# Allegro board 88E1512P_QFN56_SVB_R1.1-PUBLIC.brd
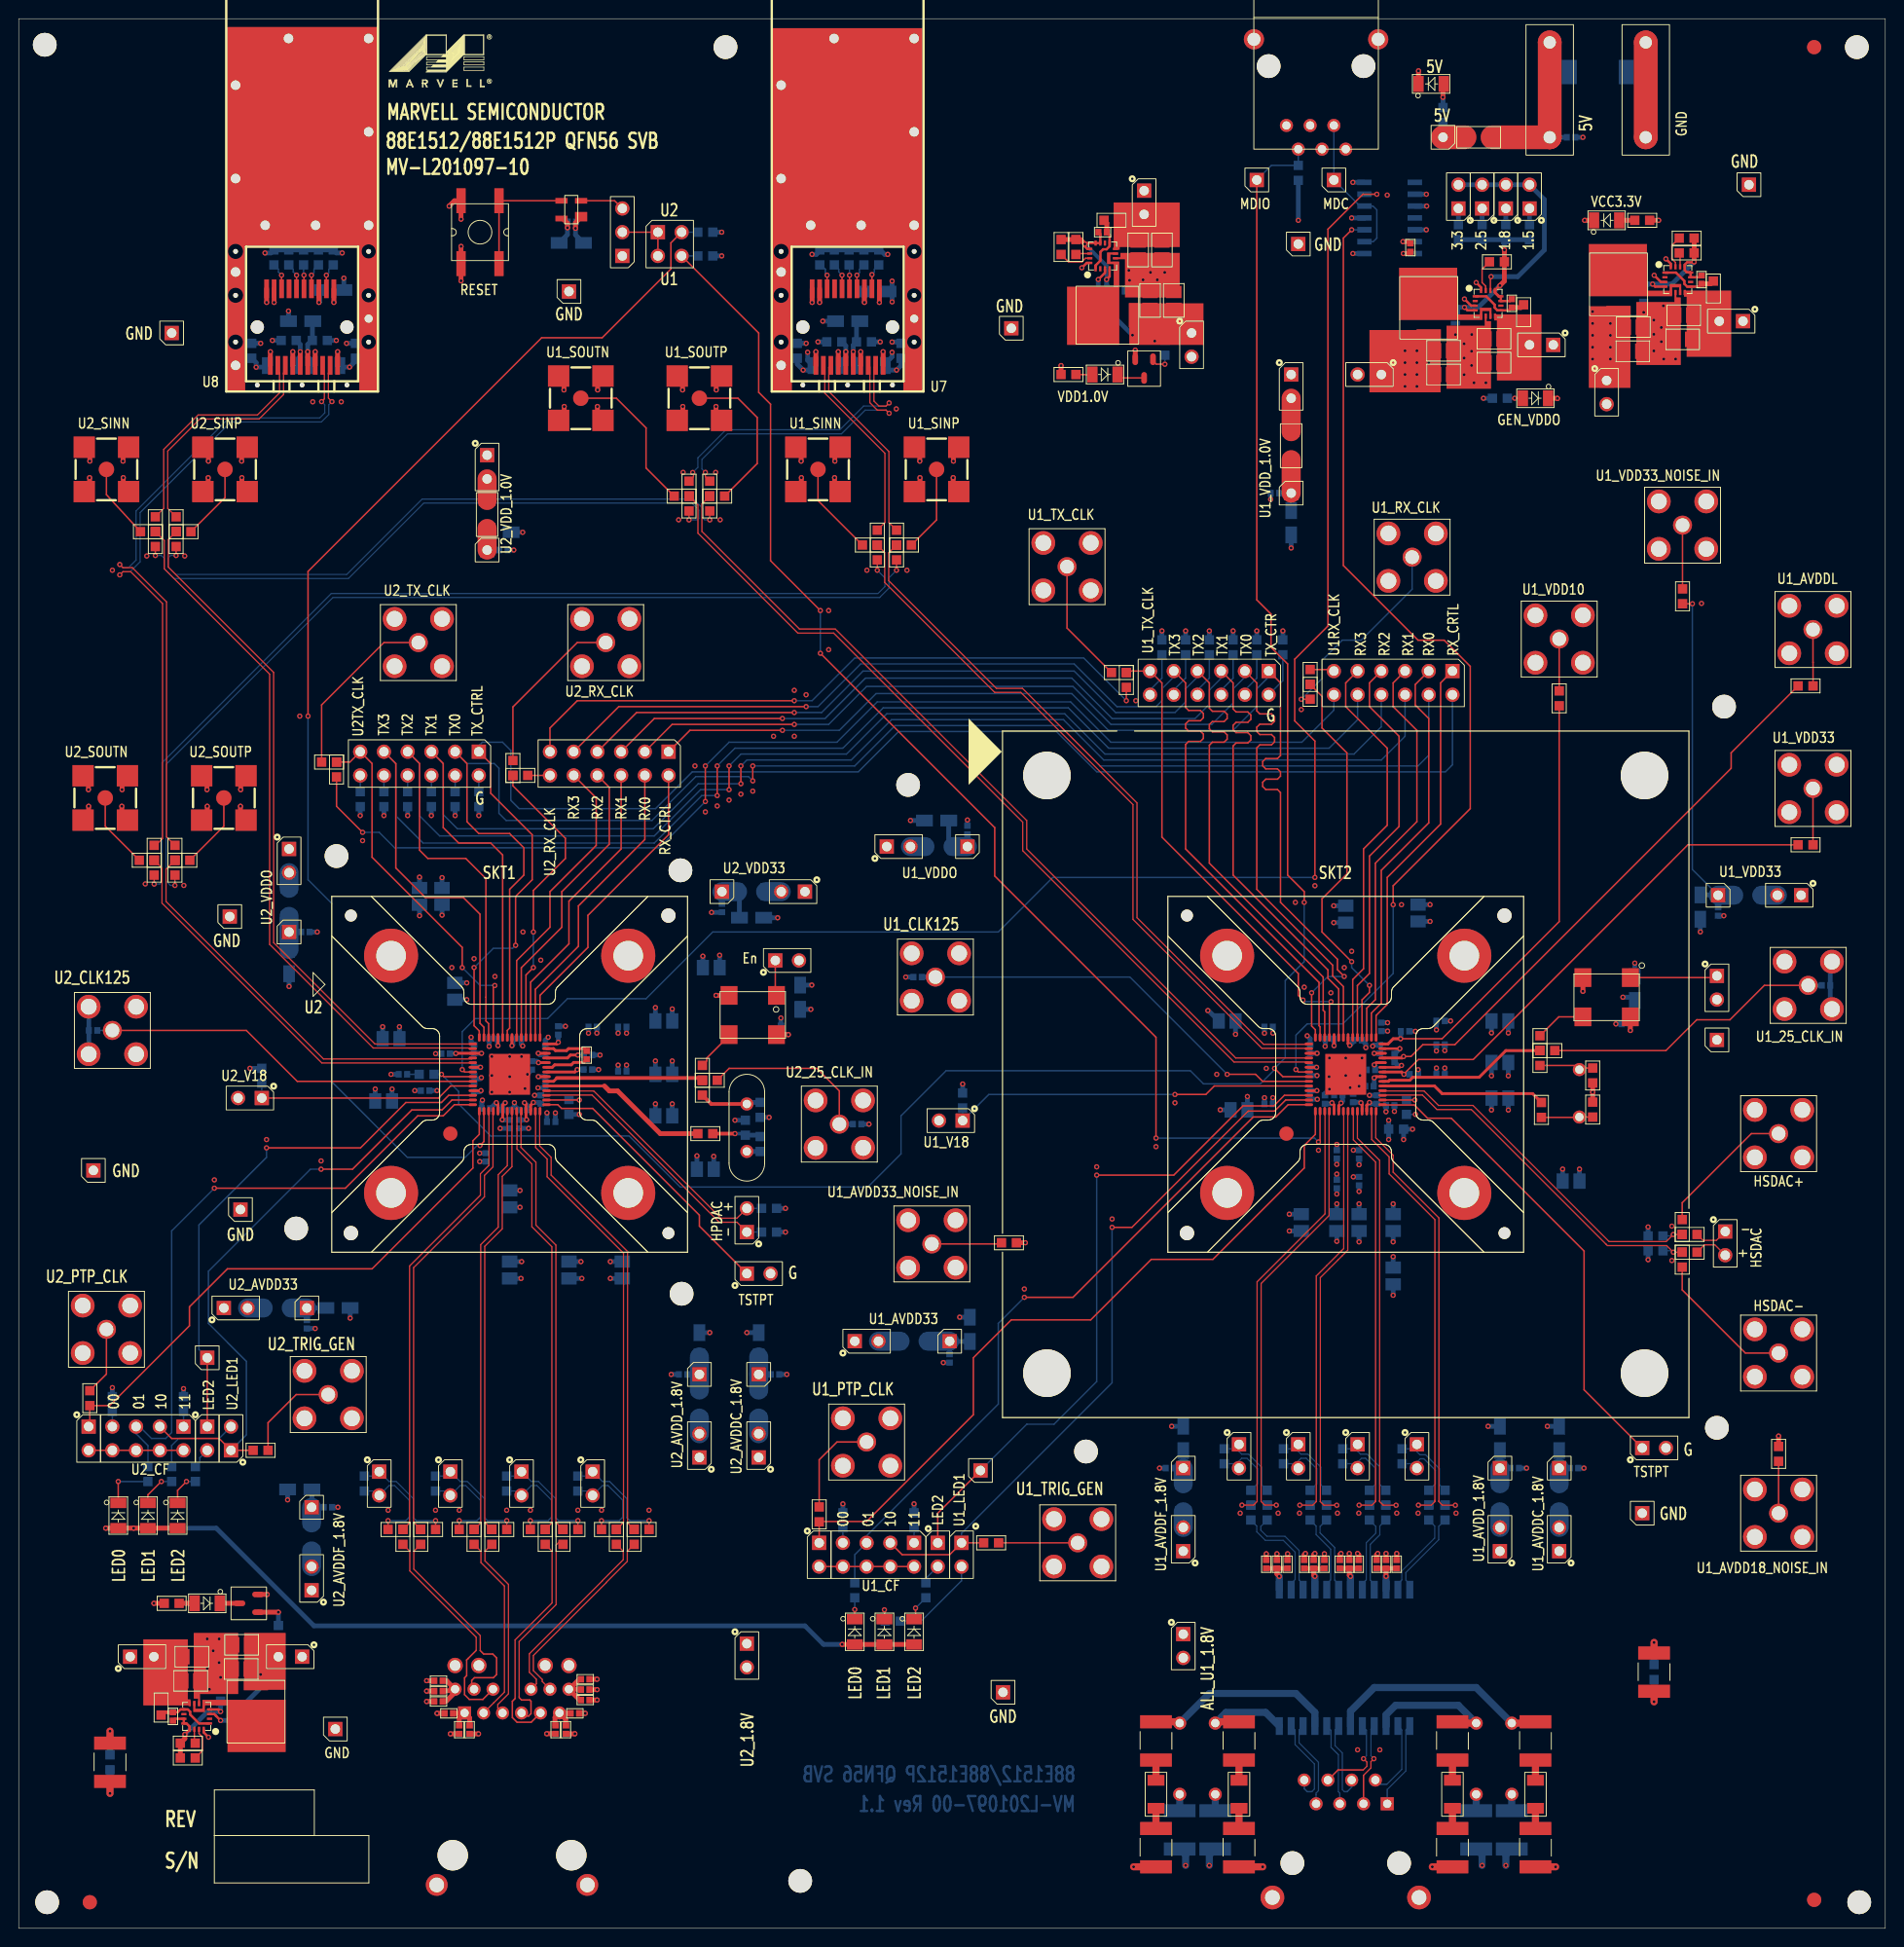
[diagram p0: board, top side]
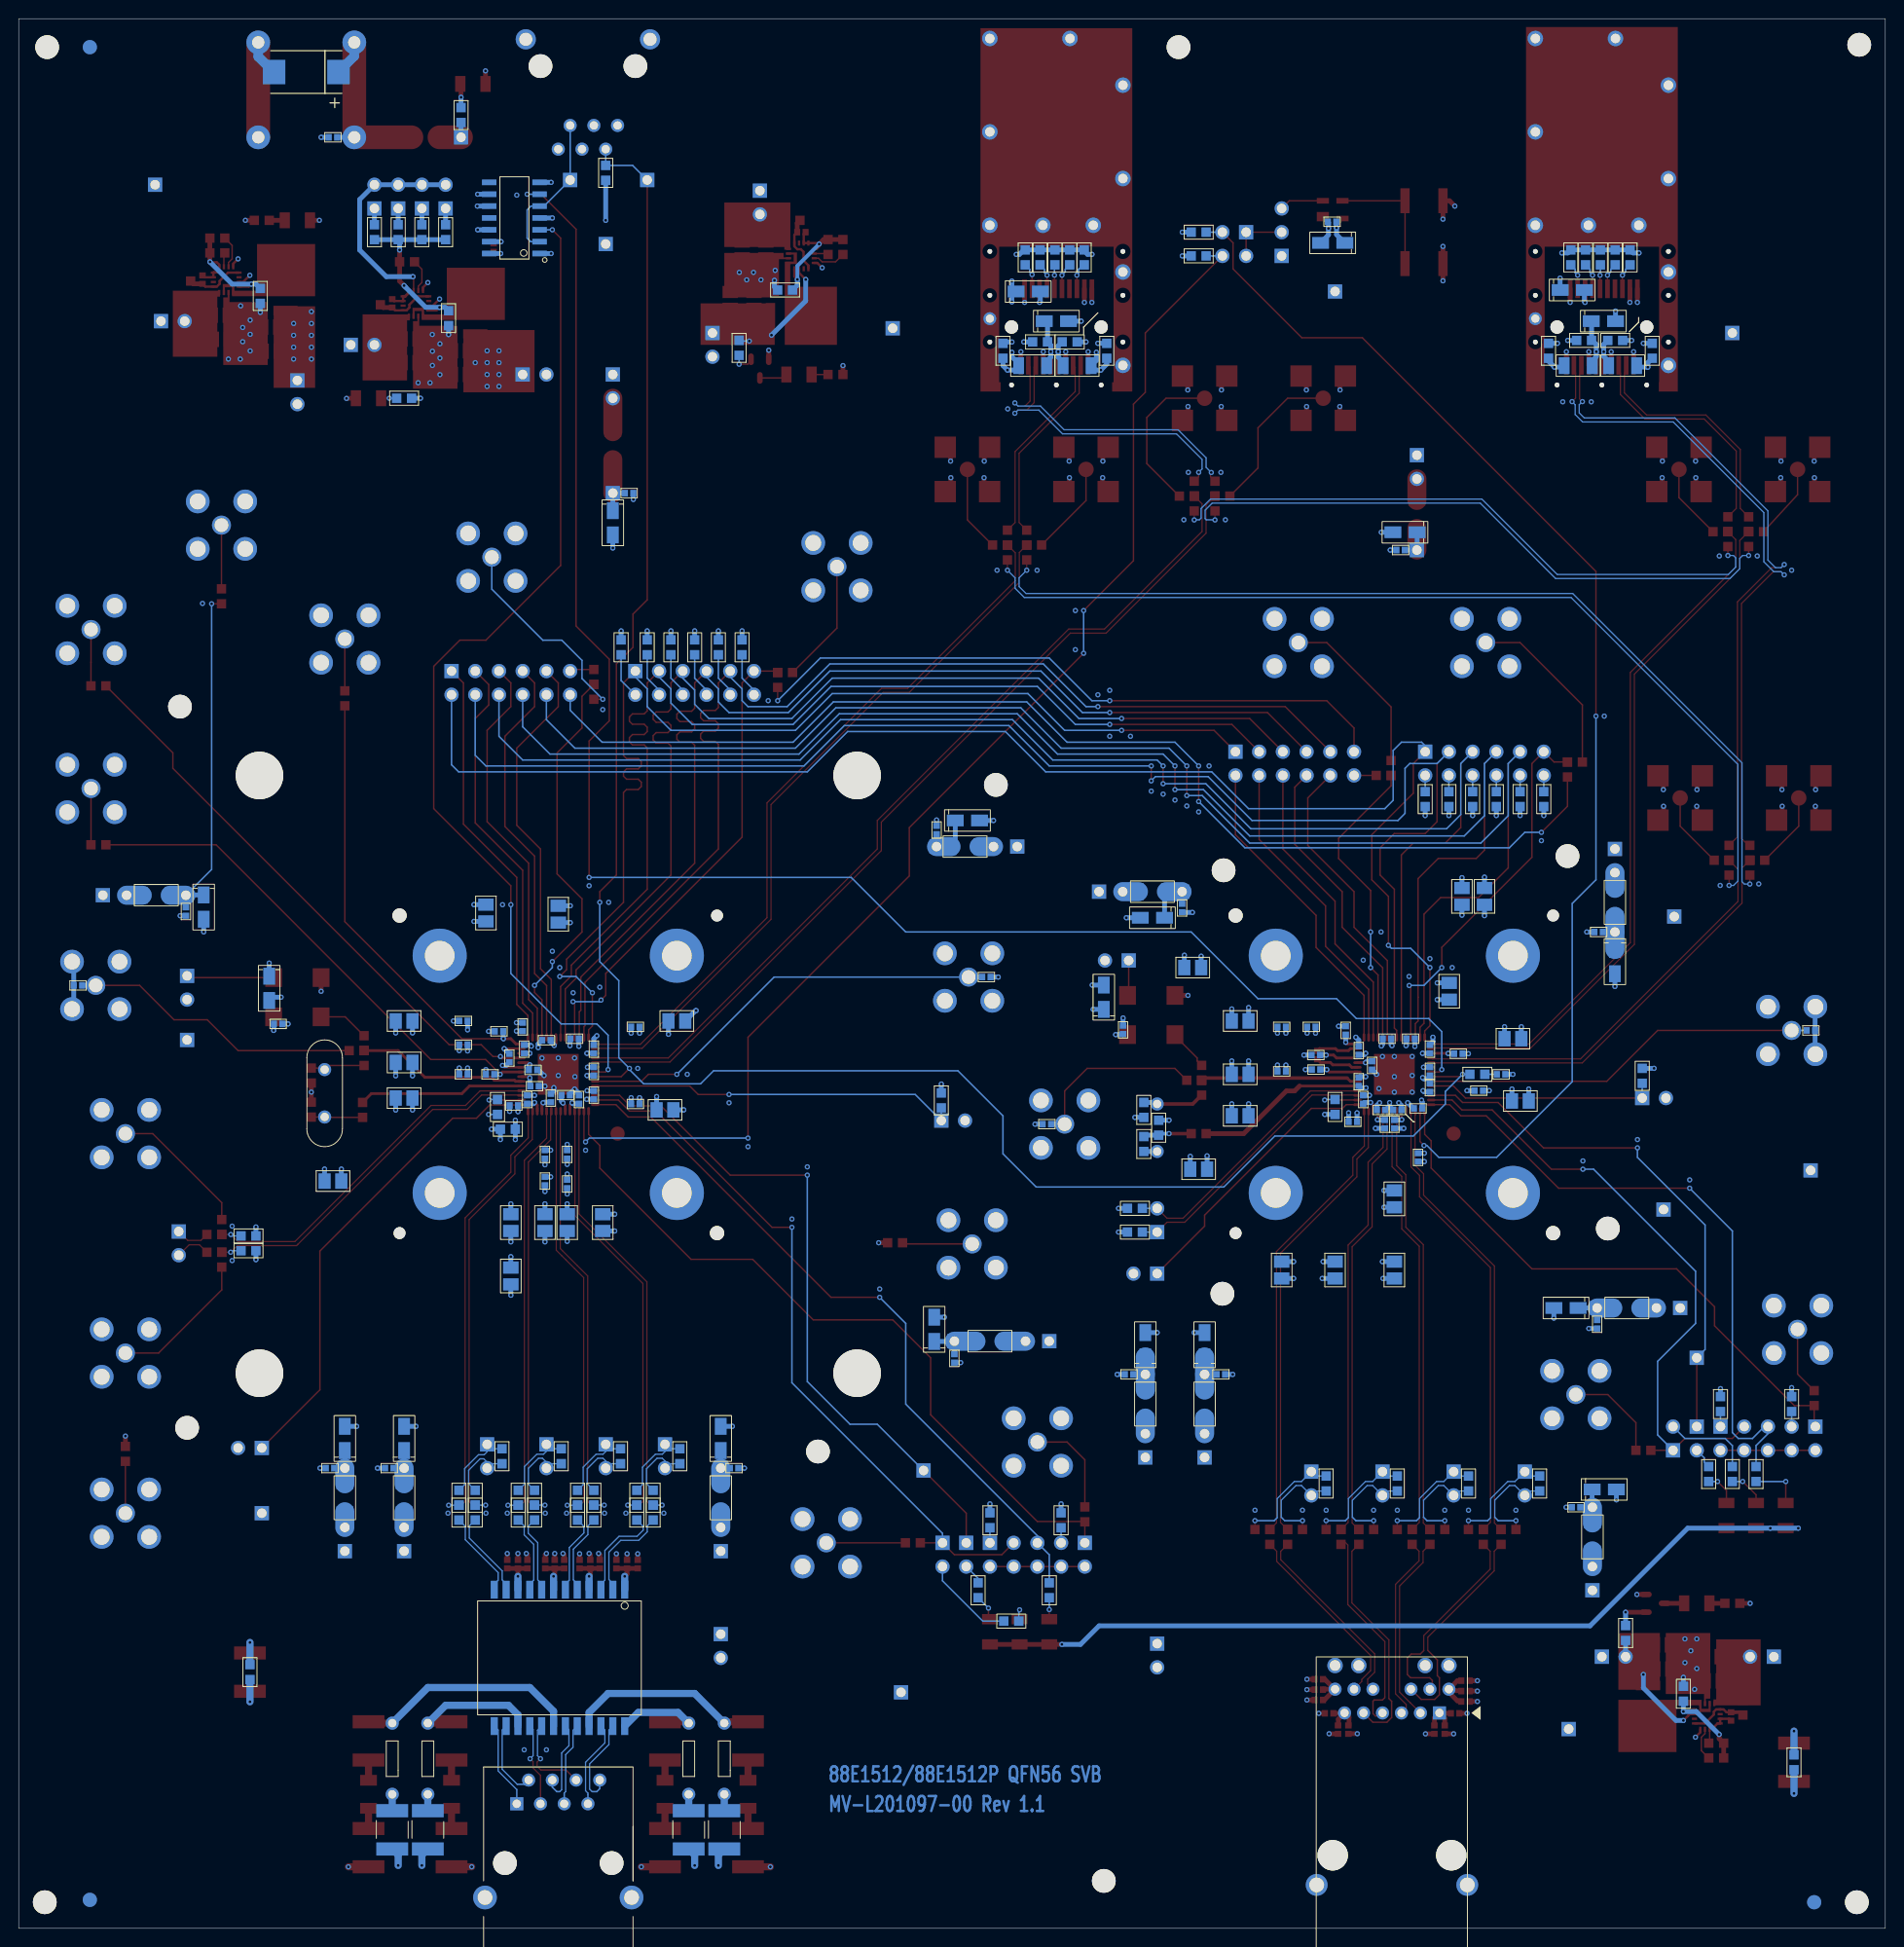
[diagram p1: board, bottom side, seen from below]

Outline 199.9 x 204.47 mm; copper layers: TOP, L2_GND, L3_PWR1, L4_PWR2, L5_GND, BOTTOM. Coordinates in mm from the lower left corner of the outline.
Outline path: 0,204.47 0,0 199.9,0 199.9,204.47 0,204.47

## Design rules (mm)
net group DIFF_U1_MDI_0: nets U1_MDI_N_0 U1_MDI_P_0
net group DIFF_U1_MDI_1: nets U1_MDI_N_1 U1_MDI_P_1
net group DIFF_U1_MDI_2: nets U1_MDI_N_2 U1_MDI_P_2
net group DIFF_U1_MDI_3: nets U1_MDI_N_3 U1_MDI_P_3
net group DIFF_U2_MDI_0: nets U2_MDI_N_0 U2_MDI_P_0
net group DIFF_U2_MDI_1: nets U2_MDI_N_1 U2_MDI_P_1
net group DIFF_U2_MDI_2: nets U2_MDI_N_2 U2_MDI_P_2
net group DIFF_U2_MDI_3: nets U2_MDI_N_3 U2_MDI_P_3
net group DIFFPAIR0: nets N17893707 N17893711
net group DIFFPAIR1: nets N17893699 N17893703
net group DIFFPAIR2: nets N17893695 N18175709
net group DIFFPAIR4: nets N18307922 N18307926
net group DIFFPAIR5: nets N18317435 N18317437
net group DIFFPAIR6: nets N18317956 N18317958
net group DIFFPAIR7: nets N18318493 N18318495
net group DIFFPAIR8: nets N18290700 N18290706
net group DIFFPAIR9: nets N18290688 N18290694
net group DIFFPAIR10: nets N18290676 N18290682
net group DIFFPAIR11: nets N18290664 N18290670
net group DIFFPAIR14: nets N17893687 N17893693
net group DIFFPAIR15: nets N18290208 N18290216
net group DIFFPAIR16: nets N18290828 N18290908
net group DIFFPAIR17: nets N19251738 N19251740
net group DIFFPAIR18: nets N19251724 N19251726
net group DIFFPAIR19: nets N19242343 N19242345
net group DIFFPAIR20: nets N19242333 N19242335
net group DIFFPAIR21: nets N19074934 N19074982
net group DIFFPAIR22: nets N17493866 N17495532
net group DIFFPAIR23: nets N18290888 N18290892
net group DIFFPAIR24: nets N16994346 N16994348
net group DIFFPAIR25: nets U1_SOUT_N_U2_SIN_N U1_SOUT_P_U2_SIN_P
net group DIFFPAIR26: nets U1_SIN_N_U2_SOUT_N U1_SIN_P_U2_SOUT_P
net group DP_N1829018: nets N18290180 N18290184
net group DP_N18290198: nets N18290198 N18290204
net group DP_N18290228: nets N18290228 N18290323
net group DP_N18290246: nets N18290246 N18290250
net group DP_N18290640: nets N18290640 N18290658
net group U1_SIN_: nets U1_SIN_N U1_SIN_P
net group U1_SOUT_: nets U1_SOUT_N U1_SOUT_P
net group U2_SIN_: nets U2_SIN_N U2_SIN_P
net group U2_SOUT_: nets U2_SOUT_N U2_SOUT_P
net group U1_RX: nets U1_RX_CTRL U1_RXD_0 U1_RXD_1 U1_RXD_2 U1_RXD_3
net group U2_RX: nets U2_RX_CTRL U2_RXD_0 U2_RXD_1 U2_RXD_2 U2_RXD_3
nets with their own width: min track width 0.508; nets GND GNDE

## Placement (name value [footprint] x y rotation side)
C1  0.1uF  [0402]  172.12 96.84 180 bottom
C2  10uF_10V  [3216P]  173.07 100.65 270 bottom
C3  0.1uF  [0402]  193.55 100.97 0 bottom
C4  10uF_10V  [3216P]  59.18 180.47 0 bottom
C5  0.1uF  [0402]  59.25 182.72 0 bottom
C6  27pF  [0603]  168.56 91.31 270 top
C7  27pF  [0603]  168.56 87.66 90 top
C8  0.1uF  [0402]  145.92 96.52 90 bottom
C9  0.1uF  [0402]  145.76 94.14 90 bottom
C10  0.1uF  [0402]  148.46 96.04 0 bottom
C11  10uF_6.3V  [0805]  158.62 97.16 0 bottom
C12  4.7uF_6.3V  [0805]  149.86 108.71 270 bottom
C13  1uF  [0402]  138.3 91.76 270 bottom
C14  0.1uF  [0402]  96.27 101.85 180 bottom
C15  0.1uF  [0603]  164.97 131.7 90 top
C16  0.1uF  [0402]  143.38 95.09 0 bottom
C17  0.1uF  [0402]  133.86 88.27 180 bottom
C18  0.1uF  [0402]  140.37 95.25 180 bottom
C19  10uF_6.3V  [0805]  142.11 108.59 270 bottom
C20  4.7uF_6.3V  [0805]  130.68 87.63 180 bottom
C21  1uF  [0402]  138.3 89.22 270 bottom
C22  0.1uF  [0603]  191.36 116.01 0 top
C23  0.1uF  [0603]  191.36 133.03 0 top
C24  0.1uF  [0402]  147.35 93.19 270 bottom
C25  0.1uF  [0402]  138.3 94.14 90 bottom
C26  10uF_6.3V  [0805]  137.35 75.56 270 bottom
C27  4.7uF_6.3V  [0805]  129.41 97.16 180 bottom
C28  1uF  [0402]  133.86 96.52 180 bottom
C29  0.1uF  [0402]  146.88 88.11 0 bottom
C30  10uF_6.3V  [0805]  147.19 69.85 270 bottom
C31  4.7uF_6.3V  [0805]  158.62 88.9 0 bottom
C32  1uF  [0402]  144.65 90.17 180 bottom
C33  0.1uF  [0402]  139.89 88.74 90 bottom
C34  0.1uF  [0402]  145.45 88.74 90 bottom
C35  0.1uF  [0402]  144.81 91.92 180 bottom
C36  0.1uF  [0402]  141.16 79.69 270 bottom
C37  10uF_6.3V  [0805]  166.24 80.01 180 bottom
C38  10uF_6.3V  [0805]  143.54 75.56 270 bottom
C39  4.7uF_6.3V  [0805]  147.19 75.56 270 bottom
C40  1uF  [0402]  143.54 82.87 270 bottom
C41  0.1uF  [0402]  141.32 89.22 180 bottom
C42  0.1uF  [0402]  141.16 82.87 270 bottom
C43  0.1uF  [0402]  142.91 88.9 90 bottom
C44  10uF_6.3V  [0805]  141.16 75.56 270 bottom
C45  1uF  [0402]  143.54 80.01 270 bottom
C46  0.1uF  [0402]  152.27 91.44 0 bottom
C47  0.1uF  [0402]  152.27 97.16 0 bottom
C48  0.1uF  [0402]  152.27 94.62 0 bottom
C49  10uF_6.3V  [0805]  158.62 92.71 0 bottom
C50  1uF  [0402]  149.42 91.44 0 bottom
C51  0.1uF  [0402]  149.03 179.96 90 top
C52  10uF_10V  [3216P]  83.69 99.7 90 bottom
C53  0.1uF  [0402]  81.63 96.2 90 bottom
C54  0.1uF  [0402]  89.79 86.11 0 bottom
C55  27pF  [0603]  79.41 87.63 270 bottom
C56  27pF  [0603]  77.82 85.73 90 bottom
C57  47pF  [0402]  41.15 91.44 180 bottom
C58  0.1uF  [0402]  48.77 91.76 270 bottom
C59  0.1uF  [0402]  57.78 96.14 90 bottom
C60  10uF_6.3V  [0805]  45.34 110.49 90 bottom
C61  10uF_6.3V  [0805]  69.09 97.16 0 bottom
C62  4.7uF_6.3V  [0805]  74.17 102.87 0 bottom
C63  0.1uF  [0402]  7.97 96.14 180 bottom
C64  1uF  [0402]  56.39 93.98 90 bottom
C65  0.1uF  [0402]  53.37 95.25 0 bottom
C66  0.1uF  [0402]  50.83 95.25 180 bottom
C67  0.1uF  [0402]  48.77 90.01 90 bottom
C68  10uF_6.3V  [0805]  42.93 110.49 90 bottom
C69  4.7uF_6.3V  [0805]  39.08 88.58 180 bottom
C70  1uF  [0402]  43.53 89.69 180 bottom
C71  0.1uF  [0402]  60.83 93.5 270 top
C72  0.1uF  [0402]  48.77 94.14 90 bottom
C73  10uF_6.3V  [0805]  39.88 95.25 180 bottom
C74  4.7uF_6.3V  [0805]  46.7 100.33 90 bottom
C75  1uF  [0402]  45.72 93.65 180 bottom
C76  0.1uF  [0402]  57.02 86.36 0 bottom
C77  10uF_6.3V  [0805]  69.09 87 0 bottom
C78  4.7uF_6.3V  [0805]  58.93 70.48 270 bottom
C79  1uF  [0402]  56.39 90.65 270 bottom
C80  0.1uF  [0402]  50.04 82.55 90 bottom
C81  0.1uF  [0402]  54.96 92.39 270 bottom
C82  0.1uF  [0402]  60.99 93.5 0 bottom
C83  0.1uF  [0402]  55.91 88.74 90 bottom
C84  10uF_6.3V  [0805]  52.58 78.11 90 bottom
C85  10uF_6.3V  [0805]  73.53 81.28 0 bottom
C86  4.7uF_6.3V  [0805]  64.64 70.48 270 bottom
C87  1uF  [0402]  50.04 87.79 180 bottom
C88  0.1uF  [0402]  54.01 87.63 180 bottom
C89  0.1uF  [0402]  52.26 87.63 0 bottom
C90  0.1uF  [0402]  53.59 86.11 270 bottom
C91  10uF_6.3V  [0805]  52.58 70.48 270 bottom
C92  1uF  [0402]  52.58 86.11 270 bottom
C93  0.1uF  [0402]  60.96 91.95 0 bottom
C94  0.1uF  [0402]  61.47 96.52 0 bottom
C95  0.1uF  [0402]  64.64 91.76 0 bottom
C96  10uF_6.3V  [0805]  69.09 91.44 0 bottom
C97  1uF  [0402]  64.64 96.52 0 bottom
C98  1uF_100V  [1812]  162.43 20.07 270 top
C99  47.3nF_2KV  [1812]  162.43 8.64 270 top
C100  1uF_100V  [1812]  153.54 20.07 270 top
C101  47.3nF_2KV  [1812]  153.54 8.64 270 top
C102  10nF  [0402]  145.42 38.99 90 top
C103  0.1uF  [0402]  147.57 38.99 90 top
C104  1000pF  [0402]  146.43 38.99 90 top
C105  1000p_3KV  [1812]  156.08 10.54 270 bottom
C106  1000pF  [0402]  143.51 38.99 90 top
C107  0.1uF  [0402]  141.48 38.99 90 top
C108  10nF  [0402]  142.49 38.99 90 top
C109  1000p_3KV  [1812]  159.89 10.54 270 bottom
C110  0.1uF  [0402]  139.83 38.99 90 top
C111  10nF  [0402]  137.67 38.99 90 top
C112  1000pF  [0402]  138.68 38.99 90 top
C113  1000p_3KV  [1812]  124.33 10.54 270 bottom
C114  0.1uF  [0402]  135.89 38.99 90 top
C115  10nF  [0402]  133.6 38.99 90 top
C116  1000pF  [0402]  134.75 38.99 90 top
C117  1000p_3KV  [1812]  128.14 10.54 270 bottom
C118  1uF_100V  [1812]  121.79 20.07 270 top
C119  47.3nF_2KV  [1812]  121.79 8.64 270 top
C120  1uF_100V  [1812]  130.68 20.07 270 top
C121  47.3nF_2KV  [1812]  130.68 8.64 270 top
C122  1000p_3KV  [1812]  175.13 27.43 270 top
C123  1000p_3KV  [1812]  9.78 17.78 270 top
C124  0.1uF  [0402]  60.67 26.67 0 top
C125  10nF  [0402]  60.67 25.56 0 top
C126  1000pF  [0402]  60.67 24.45 0 top
C127  0.1uF  [0402]  59.56 23.02 0 top
C128  10nF  [0402]  57.5 21.27 270 top
C129  1000pF  [0402]  58.61 21.27 270 top
C130  0.1uF  [0402]  46.07 23.02 180 top
C131  10nF  [0402]  47.18 21.27 270 top
C132  1000pF  [0402]  48.29 21.27 270 top
C133  0.1uF  [0402]  44.96 24.29 180 top
C134  10nF  [0402]  44.96 25.4 180 top
C135  1000pF  [0402]  44.96 26.51 180 top
C136  0.1uF  [0603]  94.81 148.11 0 top
C137  0.1uF  [0603]  91.15 148.11 180 top
C138  10uF_10V  [3216P]  88.77 172.08 180 bottom
C139  0.1uF  [0603]  90.52 169.86 0 bottom
C140  0.1uF  [0603]  83.38 168.91 90 bottom
C141  10uF_10V  [3216P]  91.79 175.26 180 bottom
C142  0.1uF  [0603]  87.34 169.86 180 bottom
C143  0.1uF  [0603]  94.49 168.91 90 bottom
C144  0.1uF  [0603]  70.99 153.35 0 top
C145  0.1uF  [0603]  74.8 153.35 180 top
C146  0.1uF  [0603]  17.65 149.54 0 top
C147  0.1uF  [0603]  13.84 149.54 180 top
C148  10uF_10V  [3216P]  30.19 172.08 180 bottom
C149  0.1uF  [0603]  32.26 170.02 0 bottom
C150  0.1uF  [0603]  36.07 168.91 90 bottom
C151  10uF_10V  [3216P]  33.53 175.42 180 bottom
C152  0.1uF  [0603]  28.92 170.02 180 bottom
C153  0.1uF  [0603]  24.96 168.91 90 bottom
C154  0.1uF  [0603]  13.72 114.36 0 top
C155  0.1uF  [0603]  17.53 114.36 180 top
C156  0.1uF  [0603]  188.47 50.8 270 top
C157  10uF_10V  [3216P]  158.62 52.45 90 bottom
C158  0.1uF  [0402]  160.21 49.28 0 bottom
C159  0.1uF  [0402]  166.24 191.77 0 bottom
C160  100uF_10V  [7343P]  169.1 198.75 0 bottom
C161  10uF_10V  [3216P]  164.97 52.45 90 bottom
C162  0.1uF  [0402]  166.56 49.28 0 bottom
C163  0.1uF  [0402]  123.29 49.28 180 bottom
C164  10uF_10V  [3216P]  124.71 52.45 90 bottom
C165  22uF_6.3V  [0805]  23.88 30.35 180 top
C166  22uF_6.3V  [0805]  23.83 27.77 180 top
C167  0.1uF  [0402]  16.52 22.69 270 top
C168  22uF_6.3V  [0805]  18.43 26.5 180 top
C169  22uF_6.3V  [0805]  18.54 29.08 180 top
C170  10uF_10V  [3216P]  72.9 62.48 90 bottom
C171  0.1uF  [0402]  71.15 59.31 180 bottom
C172  0.1uF  [0402]  80.99 59.31 0 bottom
C173  10uF_10V  [3216P]  79.25 62.48 90 bottom
C174  10uF_10V  [3216P]  30.1 46.99 180 bottom
C175  0.1uF  [0402]  33.12 45.09 0 bottom
C176  0.1uF  [0402]  101.6 117.6 90 bottom
C177  10uF_10V  [3216P]  98.3 118.62 180 bottom
C178  22uF_6.3V  [0805]  152.59 166.37 0 top
C179  22uF_6.3V  [0805]  152.59 168.91 0 top
C180  0.1uF  [0402]  159.89 173.99 90 top
C181  22uF_6.3V  [0805]  157.99 170.18 0 top
C182  10uF_10V  [3216P]  28.96 103.51 270 bottom
C183  22uF_6.3V  [0805]  157.99 167.64 0 top
C184  0.1uF  [0402]  30.7 106.68 0 bottom
C185  0.1uF  [0402]  134.52 153.67 180 bottom
C186  10uF_10V  [3216P]  136.27 150.5 270 bottom
C187  22uF_6.3V  [0805]  123.7 174.31 90 top
C188  22uF_6.3V  [0805]  121.16 174.31 90 top
C189  0.1uF  [0402]  116.08 181.61 180 top
C190  22uF_6.3V  [0805]  119.89 179.7 90 top
C191  0.1uF  [0402]  51.91 147.57 0 bottom
C192  22uF_6.3V  [0805]  122.43 179.7 90 top
C193  10uF_10V  [3216P]  51.43 149.48 0 bottom
C194  0.1uF  [0603]  178.18 142.62 90 top
C195  10uF_10V  [3216P]  180.09 109.35 270 bottom
C196  0.1uF  [0402]  181.99 108.87 270 bottom
C197  10uF_10V  [3216P]  78.49 108.2 0 bottom
C198  0.1uF  [0402]  75.31 109.25 270 bottom
C199  22uF_6.3V  [0805]  172.91 171.45 0 top
C200  22uF_6.3V  [0805]  172.86 168.86 0 top
C201  0.1uF  [0402]  180.21 176.53 90 top
C202  22uF_6.3V  [0805]  178.19 170.13 0 top
C203  0.1uF  [0603]  106.05 73.41 180 top
C204  10uF_10V  [3216P]  101.85 64.14 90 bottom
C205  22uF_6.3V  [0805]  178.31 172.72 0 top
C206  0.1uF  [0402]  99.69 61.02 270 bottom
C207  10uF_10V  [3216P]  34.19 66.42 0 bottom
C208  0.1uF  [0402]  30.86 64.67 270 bottom
CON1  RJ45_1000BASETX  [RJ-45_GIG_RA_SH2]  142.11 6.99 180 bottom
D1  LED  [1206_LED_DOT]  89.53 31.75 90 top
D2  LED  [1206_LED_DOT]  92.71 31.75 90 top
D3  LED  [1206_LED_DOT]  95.88 31.75 90 top
D4  LED  [1206_LED_DOT]  10.67 44.2 90 top
D5  LED  [1206_LED_DOT]  13.84 44.2 90 top
D6  LED  [1206_LED_DOT]  17.02 44.2 90 top
D7  LED  [1206_LED_DOT]  151.26 197.48 180 top
D8  LED  [1206_LED_DOT]  20.19 34.8 0 top
D9  LED  [1206_LED_DOT]  162.43 163.83 0 top
D10  LED  [1206_LED_DOT]  116.33 166.37 0 top
D11  LED  [1206_LED_DOT]  170.05 182.88 180 top
F1  Fuse_5A  [1206]  156.34 191.77 180 top
INTN_1  Header_1x1  [HDR_1X1]  103 49.02 0 top
INTN_2  Header_1x1  [HDR_1X1]  20.19 61.09 0 top
J1  SMA_TH_UP  [SMA5_TH_UP]  191.64 100.97 0 top
J2  SMA_TH_UP  [SMA5_TH_UP]  98.17 101.85 0 top
J3  SMA_TH_UP  [SMA5_TH_UP]  164.97 138.05 0 top
J4  SMA_TH_UP  [SMA5_TH_UP]  192.15 122.05 0 top
J5  SMA_TH_UP  [SMA5_TH_UP]  192.15 139.06 0 top
J6  SMA_TH_UP  [SMA5_TH_UP]  188.47 85.09 0 top
J7  SMA_TH_UP  [SMA5_TH_UP]  188.47 61.59 0 top
J8  SMA_TH_UP  [SMA5_TH_UP]  87.88 86.11 0 top
J9  RJ11  [RJ-11_SH]  138.94 199.39 180 top
J10  SMA_TH_UP  [SMA5_TH_UP]  10.03 96.14 0 top
J11  SMA_SMD_UP  [SMA5_SMD_UP]  98.3 156.21 90 top
J12  SMA_SMD_UP  [SMA5_SMD_UP]  85.6 156.21 90 top
J13  SMA_SMD_UP  [SMA5_SMD_UP]  60.2 163.83 90 top
J14  SMA_SMD_UP  [SMA5_SMD_UP]  72.9 163.83 90 top
J15  SMA_SMD_UP  [SMA5_SMD_UP]  22.1 156.21 270 top
J16  SMA_SMD_UP  [SMA5_SMD_UP]  9.4 156.21 270 top
J17  SMA_SMD_UP  [SMA5_SMD_UP]  9.27 121.03 90 top
J18  SMA_SMD_UP  [SMA5_SMD_UP]  21.97 121.03 90 top
J19  SMA_TH_UP  [SMA5_TH_UP]  188.47 44.45 0 top
J20  Connector_Power_Red  [CON2_PWR_400]  163.96 196.85 90 top
J21  Connector_Power_Black  [CON2_PWR_400]  174.24 196.85 90 top
J22  SMA_TH_UP  [SMA5_TH_UP]  178.18 150.24 0 top
J23  SMA_TH_UP  [SMA5_TH_UP]  97.79 73.28 270 top
J24  SMA_TH_UP  [SMA5_TH_UP]  149.23 146.81 0 top
J25  SMA_TH_UP  [SMA5_TH_UP]  42.8 137.67 0 top
J26  SMA_TH_UP  [SMA5_TH_UP]  62.86 137.67 0 top
J27  SMA_TH_UP  [SMA5_TH_UP]  112.27 145.8 0 top
J28  SMA_TH_UP  [SMA5_TH_UP]  90.8 52.07 90 top
J29  SMA_TH_UP  [SMA5_TH_UP]  9.4 64.14 0 top
J30  SMA_TH_UP  [SMA5_TH_UP]  113.41 41.28 0 top
J31  SMA_TH_UP  [SMA5_TH_UP]  33.15 57.15 0 top
JP1  Header_1x2  [HDR_1X2]  181.86 100.71 270 top
JP2  Header_1x3  [HDR_1X3]  64.64 181.61 90 top
JP3  Header_2x2  [HDR_2X2]  69.72 180.34 270 top
JP4  Header_1x2  [HDR_1X2]  99.82 86.49 180 top
JP5  Header_1x2  [HDR_1X2]  182.75 73.34 270 top
JP6  Header_1x2  [HDR_1X2]  175.13 51.44 0 top
JP7  Header_1x2  [HDR_1X2]  82.3 103.63 0 top
JP8  Header_1x2  [HDR_1X2]  24.77 88.9 180 top
JP9  Header_1x2  [HDR_1X2]  77.98 75.82 90 top
JP10  Header_1x2  [HDR_1X2]  79.25 70.1 0 top
JP11  Header_2x4  [HDR_2X4]  92.08 40.01 180 top
JP12  Header_1x2  [HDR_1X2]  98.42 40.01 270 top
JP13  Header_2x4  [HDR_2X4]  13.84 52.45 180 top
JP14  Header_1x2  [HDR_1X2]  20.19 52.45 270 top
JP15  Header_1x2  [HDR_1X2]  149.73 50.55 270 top
JP16  Header_1x2  [HDR_1X2]  143.38 50.55 270 top
JP17  Header_1x2  [HDR_1X2]  137.03 50.55 270 top
JP18  Header_1x2  [HDR_1X2]  130.68 50.55 270 top
JP19  Header_1x2  [HDR_1X2]  61.47 47.62 270 top
JP20  Header_1x2  [HDR_1X2]  53.85 47.62 270 top
JP21  Header_1x2  [HDR_1X2]  46.23 47.62 270 top
JP22  Header_1x2  [HDR_1X2]  38.61 47.62 270 top
JP23  Header_2X6  [HDR_2X6]  147.19 133.35 180 top
JP24  Header_2X6  [HDR_2X6]  63.25 124.71 180 top
JP25  Header_1x2  [HDR_1X2]  158.62 41.66 90 top
JP26  Header_1x2  [HDR_1X2]  164.97 41.66 90 top
JP27  Header_1x2  [HDR_1X2]  124.71 30.23 270 top
JP28  Header_1x2  [HDR_1X2]  124.71 41.66 90 top
JP29  Header_1x2  [HDR_1X2]  29.08 29.08 180 top
JP30  Header_1x2  [HDR_1X2]  13.21 29.08 0 top
JP31  Header_1x2  [HDR_1X2]  77.98 29.21 270 top
JP32  Header_1x2  [HDR_1X2]  72.9 51.69 90 top
JP33  Header_1x2  [HDR_1X2]  79.25 51.69 90 top
JP34  Header_1x2  [HDR_1X2]  31.37 37.47 90 top
JP35  Header_1x2  [HDR_1X2]  161.8 185.42 90 top
JP36  Header_1x2  [HDR_1X2]  159.26 185.42 90 top
JP37  Header_1x2  [HDR_1X2]  156.72 185.42 90 top
JP38  Header_1x2  [HDR_1X2]  154.18 185.42 90 top
JP39  Header_1x2  [HDR_1X2]  144.65 166.37 180 top
JP40  Header_1x2  [HDR_1X2]  94.23 115.82 0 top
JP41  Header_1x2  [HDR_1X2]  28.96 114.3 270 top
JP42  Header_1x2  [HDR_1X2]  163.07 169.54 180 top
JP43  Header_1x2  [HDR_1X2]  136.27 165.1 270 top
JP44  Header_1x2  [HDR_1X2]  125.6 169.54 270 top
JP45  Header_1x2  [HDR_1X2]  50.16 156.46 270 top
JP46  Header_1x2  [HDR_1X2]  120.52 184.78 270 top
JP47  Header_1x2  [HDR_1X2]  189.61 110.62 180 top
JP48  Header_1x2  [HDR_1X2]  82.93 111 180 top
JP49  Header_1x2  [HDR_1X2]  170.05 164.47 270 top
JP50  Header_1x2  [HDR_1X2]  90.8 62.86 0 top
JP51  Header_1x2  [HDR_1X2]  183.39 172.08 180 top
JP52  Header_1x2  [HDR_1X2]  23.24 66.42 0 top
JP53  Header_2X6  [HDR_2X6]  42.93 124.71 180 top
JP54  Header_1x2  [HDR_1X2]  22.73 52.45 90 top
JP55  Header_2X6  [HDR_2X6]  127.51 133.35 180 top
JP56  Header_1x2  [HDR_1X2]  100.97 40.01 270 top
JP57  Header_1x2  [HDR_1X2]  85.72 40.01 270 top
JP58  Header_1x2  [HDR_1X2]  7.49 52.45 270 top
L1  1uH  [1206]  91.31 167.32 180 bottom
L2  1uH  [1206]  86.55 167.32 180 bottom
L3  1uH  [1206]  32.89 167.32 180 bottom
L4  1uH  [1206]  28.13 167.32 180 bottom
L5  80,2A  [1206]  158.62 46.1 270 bottom
L6  80,2A  [1206]  164.97 46.1 270 bottom
L7  1.3uH  [D62LCB]  25.41 23.19 90 top
L8  80,2A  [1206]  124.71 46.1 270 bottom
L9  80,2A  [1206]  72.9 56.13 270 bottom
L10  80,2A  [1206]  79.25 56.13 270 bottom
L11  80,2A  [1206]  31.37 41.91 270 bottom
L12  1.3uH  [D62LCB]  151 173.51 270 top
L13  80,2A  [1206]  98.55 115.82 180 bottom
L14  80,2A  [1206]  28.96 109.86 90 bottom
L15  80,2A  [1206]  136.27 158.75 90 top
L16  1.3uH  [D62LCB]  116.59 172.72 0 top
L17  80,2A  [1206]  50.16 151.38 90 top
L18  80,2A  [1206]  185.17 110.62 0 bottom
L19  80,2A  [1206]  78.49 111 0 bottom
L20  1.3uH  [D62LCB]  171.32 176.02 270 top
L21  80,2A  [1206]  95.88 62.86 180 bottom
L22  80,2A  [1206]  27.69 66.42 180 bottom
NOREF  -  [unnamed]  70.99 67.95 0 top
NOREF#2  -  [unnamed]  135.76 85.09 0 top
NOREF#3  -  [unnamed]  182.63 130.81 0 top
NOREF#4  -  [unnamed]  2.79 201.68 0 top
NOREF#5  -  [#2]  39.66 197.17 0 top
NOREF#6  -  [unnamed]  114.3 51.05 0 top
NOREF#7  -  [unnamed]  7.62 2.79 0 top
NOREF#8  -  [unnamed]  34.04 114.81 0 top
NOREF#9  -  [#2]  0 204.47 0 top
NOREF#10  -  [unnamed]  70.87 113.28 0 top
NOREF#11  -  [unnamed]  3.05 2.79 0 top
NOREF#12  -  [unnamed]  46.23 85.09 0 top
NOREF#13  -  [unnamed]  29.72 74.93 0 top
NOREF#14  -  [#2]  0 0 90 top
NOREF#15  -  [unnamed]  192.28 201.42 0 top
NOREF#16  -  [unnamed]  95.25 122.43 0 top
NOREF#17  -  [#2]  321.44 302.26 0 top
NOREF#18  -  [unnamed]  196.85 201.42 0 top
NOREF#19  -  [unnamed]  83.69 5.08 0 top
NOREF#20  -  [#2]  10.16 246.89 0 top
NOREF#21  -  [unnamed]  192.28 3.05 0 top
NOREF#22  -  [unnamed#3]  142.11 91.44 0 top
NOREF#23  -  [#2]  -60.45 -72.39 0 top
NOREF#24  -  [unnamed]  197.1 2.79 0 top
NOREF#25  -  [#2]  65.66 -34.8 0 top
NOREF#26  -  [unnamed]  75.69 201.42 0 top
NOREF#27  -  [unnamed]  181.86 53.59 0 top
NOREF#28  -  [unnamed]  192.28 3.05 180 bottom
NOREF#29  -  [unnamed]  192.28 201.42 180 bottom
NOREF#30  -  [unnamed]  7.62 2.79 180 bottom
Q1  MMBT2222ALT1  [SOT-23_3_132]  24.64 34.8 180 top
Q2  MMBT2222ALT1  [SOT-23_3_132]  120.52 167 270 top
R1  4.7K  [0603]  73.53 179.07 180 bottom
R2  4.7K  [0603]  73.53 181.61 180 bottom
R3  0  [0603]  163.7 93.98 0 top
R4  22.1  [0603]  162.91 94.77 270 top
R5  0  [0603]  162.91 93.19 90 top
R6  0  [0603]  163.07 87.63 270 top
R8  4.99K  [0603]  101.09 88.65 270 bottom
R9  0  [0603]  147.51 85.57 180 bottom
R10  0  [0603]  178.15 75.09 270 top
R11  0  [0603]  178.94 74.3 180 top
R12  0  [0603]  178.94 72.39 180 top
R13  4.99K  [0603]  148.62 87.95 270 bottom
R14  49.9  [0603]  175.29 74.14 180 bottom
R15  49.9  [0603]  175.29 72.55 180 bottom
R16  0  [0603]  178.15 71.6 270 top
R17  0  [0603]  74.01 90.81 0 top
R18  22.1  [0603]  73.22 91.6 270 top
R19  0  [0603]  73.22 90.01 90 top
R20  0  [0603]  79.41 83.98 270 bottom
R21  0  [0603]  73.53 85.09 0 top
R22  1.5K  [0603]  137.03 187.96 90 bottom
R23  49.9  [0603]  43.69 91.44 180 bottom
R24  4.99K  [0603]  26.03 91.28 270 bottom
R25  4.99K  [0603]  58.93 87.95 270 bottom
R26  49.9  [0603]  80.36 77.09 0 bottom
R27  49.9  [0603]  80.36 74.55 0 bottom
R28  316  [0603]  89.53 36.2 90 bottom
R29  316  [0603]  93.6 32.89 0 bottom
R30  316  [0603]  97.16 36.2 90 bottom
R31  316  [0603]  13.84 48.64 90 bottom
R32  316  [0603]  16.38 48.64 90 bottom
R33  316  [0603]  18.92 48.64 90 bottom
R34  1.5  [1206]  162.43 14.35 270 top
R35  1.5  [1206]  153.54 14.35 270 top
R36  0  [0603]  152.75 44.51 90 bottom
R37  100  [0603]  148.15 50.55 270 bottom
R38  75_1/8W  [R1_8W]  156.08 18.16 90 bottom
R39  0  [0603]  146.4 46.1 90 bottom
R40  0  [0603]  152.75 46.1 90 bottom
R41  0  [0603]  151 44.51 90 bottom
R42  0  [0603]  151 46.1 90 bottom
R43  0  [0603]  146.4 44.51 90 bottom
R44  100  [0603]  141.8 50.55 270 bottom
R45  0  [0603]  144.65 44.51 90 bottom
R46  75_1/8W  [R1_8W]  159.89 18.16 90 bottom
R47  0  [0603]  144.65 46.1 90 bottom
R48  0  [0603]  140.05 46.1 90 bottom
R49  0  [0603]  140.05 44.51 90 bottom
R50  100  [0603]  135.45 50.55 270 bottom
R51  0  [0603]  138.3 44.51 90 bottom
R52  75_1/8W  [R1_8W]  124.33 18.16 90 bottom
R53  0  [0603]  138.3 46.1 90 bottom
R54  0  [0603]  133.7 46.1 90 bottom
R55  0  [0603]  133.7 44.51 90 bottom
R56  100  [0603]  129.1 50.55 270 bottom
R57  0  [0603]  131.95 44.51 90 bottom
R58  75_1/8W  [R1_8W]  128.14 18.16 90 bottom
R59  0  [0603]  131.95 46.1 90 bottom
R60  1.5  [1206]  121.79 14.35 270 top
R61  1.5  [1206]  130.68 14.35 270 top
R62  10M  [0603]  9.78 17.78 90 bottom
R63  10M  [0603]  175.13 27.43 90 bottom
R64  0  [0603]  66.71 42.7 0 top
R65  0  [0603]  65.91 41.91 90 top
R66  100  [0603]  59.88 47.62 270 bottom
R67  0  [0603]  64.01 41.91 90 top
R68  0  [0603]  63.21 42.7 180 top
R69  0  [0603]  59.09 42.7 0 top
R70  0  [0603]  58.29 41.91 90 top
R71  100  [0603]  52.26 47.62 270 bottom
R72  0  [0603]  56.39 41.91 90 top
R73  0  [0603]  55.59 42.7 180 top
R74  0  [0603]  51.47 42.7 0 top
R75  0  [0603]  50.67 41.91 90 top
R76  100  [0603]  44.64 47.62 270 bottom
R77  0  [0603]  48.77 41.91 90 top
R78  0  [0603]  47.97 42.7 180 top
R79  0  [0603]  43.85 42.7 0 top
R80  0  [0603]  43.05 41.91 90 top
R81  100  [0603]  37.02 47.62 270 bottom
R82  0  [0603]  41.15 41.91 90 top
R83  0  [0603]  40.35 42.7 180 top
R84  0  [0603]  94.01 147.32 90 top
R85  0  [0603]  94.01 148.91 270 top
R86  0  [0603]  91.95 148.91 270 top
R87  0  [0603]  91.95 147.32 90 top
R88  10K  [0603]  85.79 178.91 90 bottom
R89  10K  [0603]  87.34 178.91 90 bottom
R90  10K  [0603]  88.93 178.91 90 bottom
R91  10K  [0603]  90.52 178.91 90 bottom
R92  10K  [0603]  92.11 178.91 90 bottom
R93  0  [0603]  74.01 152.56 90 top
R94  0  [0603]  74.01 154.15 270 top
R95  0  [0603]  71.79 154.15 270 top
R96  0  [0603]  71.79 152.56 90 top
R97  0  [0603]  16.86 148.75 90 top
R98  0  [0603]  16.86 150.34 270 top
R99  0  [0603]  14.64 150.34 270 top
R100  10K  [0603]  27.34 178.91 90 bottom
R101  10K  [0603]  28.92 178.91 90 bottom
R102  10K  [0603]  30.51 178.91 90 bottom
R103  10K  [0603]  32.1 178.91 90 bottom
R104  10K  [0603]  33.69 178.91 90 bottom
R105  0  [0603]  14.64 148.75 90 top
R106  0  [0603]  16.73 113.57 90 top
R107  0  [0603]  16.73 115.16 270 top
R108  0  [0603]  14.51 115.16 270 top
R109  0  [0603]  14.51 113.57 90 top
R110  332  [0603]  16.38 34.8 0 top
R111  499  [0603]  152.53 194.15 270 bottom
R112  470  [0603]  27.81 31.62 90 bottom
R113  97.6K  [0603]  18.11 19.83 0 top
R114  0  [0603]  18.11 18.24 180 top
R115  0  [0603]  21.62 25.11 270 bottom
R116  10  [0603]  15.25 23.64 270 top
R117  332  [0603]  158.62 163.83 0 bottom
R118  0  [0603]  158.31 178.44 0 top
R119  56K  [0603]  161.8 181.61 270 bottom
R120  97.6K  [0603]  159.26 181.61 270 bottom
R121  165K  [0603]  156.72 181.61 270 bottom
R122  475K  [0603]  154.18 181.61 270 bottom
R123  10  [0603]  161.16 173.04 90 top
R124  0  [0603]  153.86 172.4 90 bottom
R125  332  [0603]  112.43 166.37 0 top
R126  18.7K  [0603]  113.22 180.02 90 top
R127  470  [0603]  122.75 169.23 270 bottom
R128  0  [0603]  111.63 180.02 90 top
R129  0  [0603]  117.82 175.42 180 bottom
R130  10  [0603]  117.03 182.88 180 top
R131  332  [0603]  173.86 182.88 180 top
R132  475K  [0603]  178.63 179.39 180 top
R133  0  [0603]  178.63 180.97 0 top
R134  0  [0603]  174.02 174.78 90 bottom
R135  10  [0603]  181.48 175.58 90 top
R136  0  [0603]  138.3 132.4 270 top
R137  0  [0603]  33.24 124.87 180 top
R138  0  [0603]  117.82 134.46 180 top
R139  0  [0603]  52.93 124.24 90 top
R140  0  [0603]  138.3 133.98 90 top
R141  0  [0603]  53.72 123.44 180 top
R142  0  [0603]  118.62 133.67 270 top
R143  0  [0603]  34.04 124.08 90 top
R145  4.7K  [0603]  95.88 43.69 270 bottom
R146  4.7K  [0603]  88.27 43.69 270 bottom
R147  4.7K  [0603]  10.03 56.13 270 bottom
R148  4.7K  [0603]  17.65 56.13 90 bottom
R149  0  [0603]  85.72 44.32 90 top
R150  0  [0603]  7.62 56.77 90 top
R151  4.7K  [0603]  36.58 120.9 270 bottom
R152  4.7K  [0603]  39.12 120.9 270 bottom
R153  4.7K  [0603]  41.66 120.9 270 bottom
R154  4.7K  [0603]  44.2 120.9 270 bottom
R155  4.7K  [0603]  46.74 120.9 270 bottom
R156  4.7K  [0603]  49.28 120.9 270 bottom
R157  4.7K  [0603]  122.43 137.16 90 bottom
R158  4.7K  [0603]  124.97 137.16 90 bottom
R159  4.7K  [0603]  130.05 137.16 90 bottom
R160  4.7K  [0603]  127.51 137.16 90 bottom
R161  4.7K  [0603]  132.59 137.16 90 bottom
R162  4.7K  [0603]  135.38 137.16 90 bottom
R163  0  [0603]  104.14 41.28 0 top
R164  0  [0603]  25.91 51.18 0 top
SKT1  SKT_QFN56_GTEC  [SKT_QFN50P800X800X100-56N_JT_OC]  52.58 91.44 0 top
SKT2  SKT_QFN56_GTEC  [SKT_QFN50P800X800X100-56N_JT_OC]  142.11 91.44 0 top
SW1  SW_PUSHBUTTON  [SWITCH_TACTILE]  49.4 181.61 270 top
TP1  Header_1x1  [HDR_1X1]  58.93 175.26 0 top
TP2  Header_1x1  [HDR_1X1]  137.03 180.34 0 top
TP3  Header_1x1  [HDR_1X1]  16.38 170.81 0 top
TP4  Header_1x1  [HDR_1X1]  23.75 76.96 0 top
TP5  Header_1x1  [HDR_1X1]  173.86 44.45 0 top
TP6  Header_1x1  [HDR_1X1]  140.84 187.2 0 top
TP7  Header_1x1  [HDR_1X1]  132.59 187.2 0 top
TP8  Header_1x1  [HDR_1X1]  105.41 25.27 0 top
TP9  Header_1x1  [HDR_1X1]  185.29 186.69 0 top
TP10  Header_1x1  [HDR_1X1]  33.91 21.34 0 top
TP11  Header_1x1  [HDR_1X1]  22.61 108.33 0 top
TP12  Header_1x1  [HDR_1X1]  106.3 171.32 0 top
TP13  Header_1x1  [HDR_1X1]  8 81.15 0 top
TP14  Header_1x1  [HDR_1X1]  158.62 49.28 270 top
TP15  Header_1x1  [HDR_1X1]  152.53 191.77 90 top
TP16  Header_1x1  [HDR_1X1]  164.97 49.28 270 top
TP17  Header_1x1  [HDR_1X1]  124.71 49.28 270 top
TP18  Header_1x1  [HDR_1X1]  72.9 59.31 270 top
TP19  Header_1x1  [HDR_1X1]  79.25 59.31 90 top
TP20  Header_1x1  [HDR_1X1]  31.37 45.09 270 top
TP21  Header_1x1  [HDR_1X1]  101.6 115.82 90 top
TP22  Header_1x1  [HDR_1X1]  28.96 106.68 270 top
TP23  Header_1x1  [HDR_1X1]  136.27 153.67 270 top
TP24  Header_1x1  [HDR_1X1]  50.16 147.57 270 top
TP25  Header_1x1  [HDR_1X1]  181.99 110.62 180 top
TP26  Header_1x1  [HDR_1X1]  75.31 111 90 top
TP27  Header_1x1  [HDR_1X1]  99.69 62.86 270 top
TP28  Header_1x1  [HDR_1X1]  30.86 66.42 270 top
TP29  Header_1x1  [HDR_1X1]  181.86 95.12 0 top
U1  88E1512P_QFN56  [QFN50P800X800X100-56N_180X180EP]  142.11 91.44 0 top
U2  88E1512P_QFN56  [QFN50P800X800X100-56N_180X180EP]  52.58 91.44 0 top
U3  MAX6337US16D3-T  [SOT-143]  59.18 184.02 180 top
U4  SN74LVC126A  [SOIC127P600X175-14AN]  146.81 183.13 0 bottom
U5  H5007B  [SOIC50P1600X551-24N]  141.99 28.96 270 bottom
U6  0826-1G1T-43-F  [RJ45-MAG_1X1_BEL_LED]  47.75 23.06 90 bottom
U7  -  [SFP_HOST]  88.77 171.45 180 top
U8  -  [SFP_HOST]  30.35 171.45 180 top
U9  88PG817B  [QFN50P300X300X100-16N]  19.06 22.69 90 top
U10  88PG817B  [QFN50P300X300X100-16N]  157.35 173.99 270 top
U11  88PG817B  [QFN50P300X300X100-16N]  116.08 179.07 0 top
U12  88PG817B  [QFN50P300X300X100-16N]  177.67 176.53 270 top
Y1  25MHZ OSC-SMD4_2.5V  [OSC4_SMD_7X5]  170.05 99.7 270 top
Y2  CRYSTAL_25MHz  [XTAL_V]  167.13 89.41 90 bottom
Y3  25MHZ OSC-SMD4_2.5V  [OSC4_SMD_7X5]  78.61 97.79 270 top
Y4  CRYSTAL_25MHz  [XTAL_V]  77.98 85.73 90 top

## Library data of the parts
C1 C3 C5-C51 C53-C137 C139 C140 C142-C147 C149 C150 C152-C156 C158 C159 C162 C163 C165-C169 C171 C172 C175 C176 C178-C181 C183-C185 C187-C192 C194 C196 C198-C203 C205 C206 C208 = CAP NP
C2 C4 C52 C138 C141 C148 C151 C157 C160 C161 C164 C170 C173 C174 C177 C182 C186 C193 C195 C197 C204 C207 = CAP P
CON1 = RJ45_1000BASETX
D1-D11 = LED
F1 = Fuse
INTN_1 INTN_2 TP1-TP29 = T POINT R
J1-J8 J10 J19 J22-J31 = SMA_TH_UP
J9 = RJ11
J11-J18 = SMA_SMD_UP
J20 J21 = Johnson Plug
JP1 JP4-JP10 JP12 JP14-JP22 JP25-JP52 JP54 JP56-JP58 = JUMPER_1X2 VERTICAL
JP2 = HEADER_1x3
JP3 = HEADER_2X2
JP11 JP13 = HEADER_2x4
JP23 JP24 JP53 JP55 = HEADER_2X6
L1-L22 = INDUCTOR
Q1 Q2 = MMBT2222ALT1
R1-R6 R8-R143 R145-R164 = R
SKT1 SKT2 = SKT_QFN56_GTEC
SW1 = SW_PUSHBUTTON
U1 U2 = 88E1512P_QFN56
U3 = MAX6337
U4 = SN74LVC126A
U5 = H5007B
U6 = 0826-1G1T-43-F
U7 U8 = SFP_HOST
U9-U12 = 88PG8x7B-QFN16
Y1 Y3 = OSC4_SMD_7X5
Y2 Y4 = CRYSTAL_25MHZ

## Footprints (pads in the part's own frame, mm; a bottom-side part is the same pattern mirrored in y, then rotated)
0402
  rect 0.65x0.7 smd: 1(-0.45,0) 2(0.45,0)
0603
  rect 1x1 smd: 1(-0.8,0) 2(0.8,0)
0805
  rect 1.3x1.65 smd: 1(-0.9,0) 2(0.9,0)
1206
  rect 1.15x1.8 smd: 1(-1.5,0) 2(1.5,0)
1206_LED_DOT
  rect 1.1x1.7 smd: 1(-1.35,0) 2(1.35,0)
1812
  rect 1.4x3.4 smd: 1(-2.05,0) 2(2.05,0)
3216P
  rect 1.8x1.25 smd: 1(-1.3,0) 2(1.3,0)
7343P
  rect 2.4x2.6 smd: 1(-3.444,0) 2(3.444,0)
CON2_PWR_400
  round 2.54 hole 1.321: 1(-5.08,0) 2(5.08,0)
D62LCB
  rect 1x2.6 smd: 1(-2.8,0) 2(2.8,0)
HDR_1X1
  rect 1.524x1.524 hole 1.016: 1(0,0)
HDR_1X2
  rect 1.524x1.524 hole 1.016: 1(-1.27,0)
  round 1.524 hole 1.016: 2(1.27,0)
HDR_1X3
  rect 1.524x1.524 hole 1.016: 1(-2.54,0)
  round 1.524 hole 1.016: 2(0,0) 3(2.54,0)
HDR_2X2
  rect 1.524x1.524 hole 1.016: 1(-1.27,-1.27)
  round 1.524 hole 1.016: 2(-1.27,1.27) 3(1.27,-1.27) 4(1.27,1.27)
HDR_2X4
  rect 1.524x1.524 hole 1.016: 1(-3.81,-1.27)
  round 1.524 hole 1.016: 2(-3.81,1.27) 3(-1.27,-1.27) 4(-1.27,1.27) 5(1.27,-1.27) 6(1.27,1.27) 7(3.81,-1.27) 8(3.81,1.27)
HDR_2X6
  rect 1.524x1.524 hole 1.016: 1(-6.35,-1.27)
  round 1.524 hole 1.016: 2(-6.35,1.27) 3(-3.81,-1.27) 4(-3.81,1.27) 5(-1.27,-1.27) 6(-1.27,1.27) 7(1.27,-1.27) 8(1.27,1.27) 9(3.81,-1.27) 10(3.81,1.27) 11(6.35,-1.27) 12(6.35,1.27)
OSC4_SMD_7X5
  rect 2x1.8 smd: 1(-2.1,2.54) 2(-2.1,-2.54) 3(2.1,-2.54) 4(2.1,2.54)
QFN50P300X300X100-16N
  rect 0.25x0.65 smd: 1(-0.75,-1.325)
  rect 0.25x0.55 smd: 2(-0.25,-1.375) 3(0.25,-1.375) 4(0.75,-1.375) 9(0.75,1.375) 10(0.25,1.375) 11(-0.25,1.375) 12(-0.75,1.375)
  rect 0.55x0.25 smd: 5(1.375,-0.75) 6(1.375,-0.25) 7(1.375,0.25) 8(1.375,0.75) 13(-1.375,0.75) 14(-1.375,0.25) 15(-1.375,-0.25) 16(-1.375,-0.75)
QFN50P800X800X100-56N_180X180EP
  oval 0.9x0.3 smd: 1(-3.95,3.25) 2(-3.95,2.75) 3(-3.95,2.25) 4(-3.95,1.75) 5(-3.95,1.25) 6(-3.95,0.75) 7(-3.95,0.25) 8(-3.95,-0.25) 9(-3.95,-0.75) 10(-3.95,-1.25) 11(-3.95,-1.75) 12(-3.95,-2.25) 13(-3.95,-2.75) 14(-3.95,-3.25) 29(3.95,-3.25) 30(3.95,-2.75) 31(3.95,-2.25) 32(3.95,-1.75) 33(3.95,-1.25) 34(3.95,-0.75) 35(3.95,-0.25) 36(3.95,0.25) 37(3.95,0.75) 38(3.95,1.25) 39(3.95,1.75) 40(3.95,2.25) 41(3.95,2.75) 42(3.95,3.25)
  oval 0.3x0.9 smd: 15(-3.25,-3.95) 16(-2.75,-3.95) 17(-2.25,-3.95) 18(-1.75,-3.95) 19(-1.25,-3.95) 20(-0.75,-3.95) 21(-0.25,-3.95) 22(0.25,-3.95) 23(0.75,-3.95) 24(1.25,-3.95) 25(1.75,-3.95) 26(2.25,-3.95) 27(2.75,-3.95) 28(3.25,-3.95) 43(3.25,3.95) 44(2.75,3.95) 45(2.25,3.95) 46(1.75,3.95) 47(1.25,3.95) 48(0.75,3.95) 49(0.25,3.95) 50(-0.25,3.95) 51(-0.75,3.95) 52(-1.25,3.95) 53(-1.75,3.95) 54(-2.25,3.95) 55(-2.75,3.95) 56(-3.25,3.95)
  rect 4.37x4.37 smd: 57(0,0)
R1_8W
  round 1.397 hole 0.889: 1(-3.81,0) 2(3.81,0)
RJ45-MAG_1X1_BEL_LED
  round 3.251 hole 3.251 unplated: (-15.24,-1.27) (-15.24,11.43)
  rect 1.397x1.397 hole 0.889: 1(0,0)
  round 1.397 hole 0.889: 2(0,2.032) 3(0,4.064) 4(0,6.096) 5(0,8.128) 6(0,10.16) 7(2.54,-1.016) 8(2.54,1.016) 9(2.54,3.048) 10(2.54,7.112) 11(2.54,9.144) 12(2.54,11.176)
  round 1.651 hole 1.143: 13(5.08,-1.016) 14(5.08,1.524) 15(5.08,8.636) 16(5.08,11.176)
  round 2.337 hole 1.575: 17(-18.415,-2.985) 18(-18.415,13.145)
RJ-11_SH
  round 2.54 hole 3.251 unplated: (-5.08,0) (5.08,0)
  round 1.397 hole 0.889: 1(-3.175,8.89) 2(-1.905,6.35) 3(-0.635,8.89) 4(0.635,6.35) 5(1.905,8.89) 6(3.175,6.35)
  round 2.159 hole 1.397: 7(-6.655,-2.87) 8(6.655,-2.87)
RJ-45_GIG_RA_SH2
  round 2.54 hole 3.251 unplated: (-5.715,0) (5.715,0)
  rect 1.397x1.397 hole 0.889: 1(-4.445,6.35)
  round 1.397 hole 0.889: 2(-3.175,8.89) 3(-1.905,6.35) 4(-0.635,8.89) 5(0.635,6.35) 6(1.905,8.89) 7(3.175,6.35) 8(4.445,8.89)
  round 2.54 hole 1.575: 9(-7.849,-3.683) 10(7.849,-3.683)
SFP_HOST
  round 0.508 hole 0.94 unplated: (-7.125,1.6) (-7.125,-3.4) (-7.125,-8.1) (-4.8,6.2) (0,6.2) (4.8,6.2) (7.125,1.6) (7.125,-3.4) (7.125,-8.1)
  round 1.422 hole 1.549 unplated: (-4.8,0) (4.8,0)
  rect 0.5x2 smd: 1(-3.4,-4.1) 2(-2.6,-4.1) 3(-1.8,-4.1) 4(-1,-4.1) 5(-0.2,-4.1) 6(0.6,-4.1) 7(1.4,-4.1) 8(2.2,-4.1) 9(3,-4.1) 10(3.8,-4.1) 11(3.4,4.1) 12(2.6,4.1) 13(1.8,4.1) 14(1,4.1) 15(0.2,4.1) 16(-0.6,4.1) 17(-1.4,4.1) 18(-2.2,4.1) 19(-3,4.1) 20(-3.8,4.1)
  round 1.372 hole 0.864: 23(-7.125,-0.9)
  round 1.651 hole 1.016: 33(7.125,4.1) 34(7.125,-5.9) 35(-7.125,-10.9) 36(-1.445,-10.9) 37(3.955,-10.9) 38(7.125,-15.9) 39(-7.125,-20.9) 40(7.125,-25.9) 41(-7.125,-30.9) 42(1.455,-30.9)
SKT_QFN50P800X800X100-56N_JT_OC
  round 1.27 hole 1.854 unplated: (-17,17) (17,-17)
  round 1.524 hole 1.6 unplated: (-17,-17) (17,17)
  round 5.791 hole 3.175: 1(-12.7,12.7) 2(12.7,12.7) 3(-12.7,-12.7) 4(12.7,-12.7)
SMA5_SMD_UP
  round 1.651 smd: 1(0,0)
  rect 2.286x2.286 smd: 2(-2.375,2.375) 3(2.375,2.375) 4(2.375,-2.375) 5(-2.375,-2.375)
SMA5_TH_UP
  round 2.032 hole 1.473: 1(0,0)
  round 2.54 hole 1.702: 2(-2.54,2.54) 3(-2.54,-2.54) 4(2.54,-2.54) 5(2.54,2.54)
SOIC50P1600X551-24N
  rect 1.905x0.762 smd: 1(-7.303,6.985) 2(-7.303,5.715) 3(-7.303,4.445) 4(-7.303,3.175) 5(-7.303,1.905) 6(-7.303,0.635) 7(-7.303,-0.635) 8(-7.303,-1.905) 9(-7.303,-3.175) 10(-7.303,-4.445) 11(-7.303,-5.715) 12(-7.303,-6.985) 13(7.303,-6.985) 14(7.303,-5.715) 15(7.303,-4.445) 16(7.303,-3.175) 17(7.303,-1.905) 18(7.303,-0.635) 19(7.303,0.635) 20(7.303,1.905) 21(7.303,3.175) 22(7.303,4.445) 23(7.303,5.715) 24(7.303,6.985)
SOIC127P600X175-14AN
  rect 1.55x0.6 smd: 1(-2.7,3.81) 2(-2.7,2.54) 3(-2.7,1.27) 4(-2.7,0) 5(-2.7,-1.27) 6(-2.7,-2.54) 7(-2.7,-3.81) 8(2.7,-3.81) 9(2.7,-2.54) 10(2.7,-1.27) 11(2.7,0) 12(2.7,1.27) 13(2.7,2.54) 14(2.7,3.81)
SOT-23_3_132
  oval 1.25x0.6 smd: 1(-1,0.95) 2(-1,-0.95) 3(1,0)
SOT-143
  rect 1.3x1 smd: 1(-1.05,0.75)
  rect 1.3x0.6 smd: 2(-1.05,-0.95) 3(1.05,-0.95) 4(1.05,0.95)
SWITCH_TACTILE
  rect 2.667x0.991 smd: 1(-3.365,2.032) 2(-3.365,-2.032) 3(3.365,-2.032) 4(3.365,2.032)
unnamed
  round 2.54 hole 3.251 unplated: (0,0)
unnamed#3
  round 5.08 hole 6.858 unplated: (-32,32) (-32,-32) (32,32) (32,-32)
XTAL_V
  round 1.397 hole 0.889: 1(-2.54,0) 2(2.54,0)

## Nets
GND: C1.2 C2.2 C3.2 C4.2 C5.2 C6.2 C7.2 C8.2 C9.2 C10.2 C11.2 C12.2 C13.2 C14.2 C16.2 C17.2 C18.2 C19.2 C20.2 C21.2 C25.2 C26.2 C27.2 C28.2 C29.2 C30.2 C31.2 C32.2 C33.2 C34.2 C35.2 C36.2 C37.2 C38.2 C39.2 C40.2 C41.2 C42.2 C43.2 C44.2 C45.2 C46.2 C47.2 C48.2 C49.2 C50.2 C51.2 C52.2 C53.2 C54.2 C55.2 C56.2 C57.2 C58.2 C59.2 C60.2 C61.2 C62.2 C63.2 C64.2 C65.2 C66.2 C67.2 C68.2 C69.2 C70.2 C72.2 C73.2 C74.2 C75.2 C76.2 C77.2 C78.2 C79.2 C80.2 C81.2 C82.2 C83.2 C84.2 C85.2 C86.2 C87.2 C88.2 C89.2 C90.2 C91.2 C92.2 C93.2 C94.2 C95.2 C96.2 C97.2 C102.2 C103.2 C104.2 C106.2 C107.2 C108.2 C110.2 C111.2 C112.2 C114.2 C115.2 C116.2 C122.1 C123.1 C124.2 C125.2 C126.2 C127.2 C128.2 C129.2 C130.2 C131.2 C132.2 C133.2 C134.2 C135.2 C138.2 C139.2 C140.2 C141.2 C142.2 C143.2 C148.2 C149.2 C150.2 C151.2 C152.2 C153.2 C157.2 C158.2 C159.2 C160.2 C161.2 C162.2 C163.2 C164.2 C165.2 C166.2 C168.1 C169.1 C170.2 C171.2 C172.2 C173.2 C174.2 C175.2 C176.2 C177.2 C178.2 C179.2 C181.1 C182.2 C183.1 C184.2 C185.2 C186.2 C187.2 C188.2 C190.1 C191.2 C192.1 C193.2 C195.2 C196.2 C197.2 C198.2 C199.2 C200.2 C202.1 C204.2 C205.1 C206.2 C207.2 C208.2 D7.2 D9.2 D11.2 J1.2 J1.3 J1.4 J1.5 J2.2 J2.3 J2.4 J2.5 J3.2 J3.3 J3.4 J3.5 J4.2 J4.3 J4.4 J4.5 J5.2 J5.3 J5.4 J5.5 J6.2 J6.3 J6.4 J6.5 J7.2 J7.3 J7.4 J7.5 J8.2 J8.3 J8.4 J8.5 J9.3 J9.4 J10.2 J10.3 J10.4 J10.5 J11.2 J11.3 J11.4 J11.5 J12.2 J12.3 J12.4 J12.5 J13.2 J13.3 J13.4 J13.5 J14.2 J14.3 J14.4 J14.5 J15.2 J15.3 J15.4 J15.5 J16.2 J16.3 J16.4 J16.5 J17.2 J17.3 J17.4 J17.5 J18.2 J18.3 J18.4 J18.5 J19.2 J19.3 J19.4 J19.5 J21.1 J21.2 J22.2 J22.3 J22.4 J22.5 J23.2 J23.3 J23.4 J23.5 J24.2 J24.3 J24.4 J24.5 J25.2 J25.3 J25.4 J25.5 J26.2 J26.3 J26.4 J26.5 J27.2 J27.3 J27.4 J27.5 J28.2 J28.3 J28.4 J28.5 J29.2 J29.3 J29.4 J29.5 J30.2 J30.3 J30.4 J30.5 J31.2 J31.3 J31.4 J31.5 JP1.2 JP2.1 JP4.2 JP6.2 JP7.2 JP8.2 JP10.2 Q1.2(EMITTER) Q2.2(EMITTER) R13.2 R14.2 R15.2 R25.2 R26.2 R27.2 R62.2 R63.2 R115.1 R124.1 R129.1 R134.1 R146.1 R147.1 R151.2 R152.2 R153.2 R154.2 R155.2 R156.2 R157.2 R158.2 R159.2 R160.2 R161.2 R162.2 SW1.2 SW1.3 TP1.1(TP) TP2.1(TP) TP3.1(TP) TP4.1(TP) TP5.1(TP) TP8.1(TP) TP9.1(TP) TP10.1(TP) TP11.1(TP) TP12.1(TP) TP13.1(TP) U1.57(EPAD) U2.57(EPAD) U3.1(GND0) U4.7(GND) U4.9(3A) U4.10(OE3) U4.12(4A) U4.13(OE4) U7.1(VEET#1) U7.3(TX DISABLE) U7.9(VEER#9) U7.10(VEER#10) U7.11(VEER#11) U7.14(VEER#14) U7.17(VEET#17) U7.20(VEET#20) U8.1(VEET#1) U8.3(TX DISABLE) U8.9(VEER#9) U8.10(VEER#10) U8.11(VEER#11) U8.14(VEER#14) U8.17(VEET#17) U8.20(VEET#20) U9.6(PGND) U9.16(LFB) U10.6(PGND) U10.16(LFB) U11.6(PGND) U11.16(LFB) U12.6(PGND) U12.16(LFB) Y1.2(GND) Y3.2(GND)
GNDE: C99.2 C101.2 C105.2 C109.2 C113.2 C117.2 C119.2 C121.2 C122.2 C123.2 CON1.9(SHIELD1) CON1.10(SHIELD2) J9.7(SHIELD1) J9.8(SHIELD2) R62.1 R63.1 U6.17(GND#17) U6.18(GND#18) U7.23(GND#23) U7.33(GND#33) U7.34(GND#34) U7.35(GND#35) U7.36(GND#36) U7.37(GND#37) U7.38(GND#38) U7.39(GND#39) U7.40(GND#40) U7.41(GND#41) U7.42(GND#42) U8.23(GND#23) U8.33(GND#33) U8.34(GND#34) U8.35(GND#35) U8.36(GND#36) U8.37(GND#37) U8.38(GND#38) U8.39(GND#39) U8.40(GND#40) U8.41(GND#41) U8.42(GND#42)
SGND_U9: C167.2 R113.1 R114.2 R115.2 U9.4(CG) U9.11(SHDN) U9.12(SDI) U9.13(SGND)
SGND_U10: C180.2 R118.2 R119.2 R120.2 R121.2 R122.2 R124.2 U10.4(CG) U10.11(SHDN) U10.12(SDI) U10.13(SGND)
SGND_U11: C189.2 R126.2 R128.2 R129.2 U11.4(CG) U11.11(SHDN) U11.12(SDI) U11.13(SGND)
SGND_U12: C201.2 R132.1 R133.2 R134.2 U12.4(CG) U12.11(SHDN) U12.12(SDI) U12.13(SGND)
VCC_3.3V: C140.1 C141.1 C143.1 C150.1 C151.1 C153.1 C199.1 C200.1 D1.1 D2.1 D3.1 D4.1 D5.1 D6.1 J9.1 J9.6 JP49.1 L1.1 L2.2 L3.1 L4.2 L20.2 R88.2 R89.2 R90.2 R91.2 R92.2 R100.2 R101.2 R102.2 R103.2 R104.2 R110.1 R125.1 R131.1 U12.3(SFB)
VCC_5V: F1.2 JP30.1 JP42.1 JP46.1 JP51.1 R111.2 TP15.1(TP)
VDD_1.0V: C187.1 C188.1 JP44.1 L16.2 R127.1 U11.3(SFB)
GEN_VDDO: C1.1 C2.1 C4.1 C5.1 C51.1 C52.1 C53.1 C178.1 C179.1 JP39.1 L12.2 R1.1 R2.1 R8.1 R22.1 R24.1 R117.1 R145.1 R148.2 U3.4(VCC) U4.1(OE1) U4.4(OE2) U4.14(VCC) U10.3(SFB) Y1.4(VCC0) Y3.4(VCC0)
MDC: J9.2 TP6.1(TP) U4.2(1A) U4.5(2A)
MDIO: J9.5 R22.2 R23.1 TP7.1(TP) U1.8(MDIO) U2.8(MDIO)
U1_1.8V: JP25.1 JP26.1 JP27.1 JP28.1
U1_AVDD_1.8V: C33.1 C34.1 C35.1 C36.1 C37.1 C38.1 C39.1 C40.1 C156.1 C157.1 C158.1 L5.1 R9.2 TP14.1(TP) U1.19(AVDD18#19) U1.26(AVDD18#26) U1.38(AVDD18#38)
U1_AVDD_3.3V: C41.1 C42.1 C43.1 C44.1 C45.1 C203.1 C204.1 C206.1 L21.1 TP27.1(TP) U1.20(AVDD33#20) U1.25(AVDD33#25)
U1_AVDDC_1.8V: C29.1 C30.1 C31.1 C32.1 C161.1 C162.1 L6.1 TP16.1(TP) U1.35(AVDDC18)
U1_AVDDF_1.8V: C25.1 C26.1 C27.1 C28.1 C163.1 C164.1 L8.1 TP17.1(TP) U1.3(AVDD18#3)
U1_CLK125: C14.1 J2.1 U1.9(CLK125)
U1_CONFIG: JP57.1 R149.1 U1.15(CONFIG)
U1_LED_0: JP11.5 R28.2 U1.14(LED[0])
U1_LED_1: JP11.3 JP56.1 R163.1 U1.13(LED[1])
U1_LED_2: INTN_1.1(TP) JP12.1 U1.12(LED[2]/INTN)
U1_MDC: U1.7(MDC) U4.3(1Y)
U1_MDI_N_0: R41.2 R42.1 U1.27(MDIN[0])
U1_MDI_N_1: R45.2 R47.1 U1.23(MDIN[1])
U1_MDI_N_2: R51.2 R53.1 U1.21(MDIN[2])
U1_MDI_N_3: R57.2 R59.1 U1.17(MDIN[3])
U1_MDI_P_0: R36.2 R40.1 U1.28(MDIP[0])
U1_MDI_P_1: R39.1 R43.2 U1.24(MDIP[1])
U1_MDI_P_2: R48.1 R49.2 U1.22(MDIP[2])
U1_MDI_P_3: R54.1 R55.2 U1.18(MDIP[3])
U1_RESETN: JP3.4 R1.2 U1.16(RESETN)
U1_RX_CLK: R136.1 R140.1 U1.46(RX_CLK)
U1_RX_CLK1: JP23.11 R140.2
U1_RX_CTRL: JP23.1 U1.43(RX_CTRL)
U1_RXD_0: JP23.3 U1.44(RXD[0])
U1_RXD_1: JP23.5 U1.45(RXD[1])
U1_RXD_2: JP23.7 U1.47(RXD[2])
U1_RXD_3: JP23.9 U1.48(RXD[3])
U1_SIN_N: C137.1 R86.2 R87.2 U1.2(S_INN)
U1_SIN_N_U2_SOUT_N: R87.1 R109.1
U1_SIN_P: C136.1 R84.2 R85.2 U1.1(S_INP)
U1_SIN_P_U2_SOUT_P: R84.1 R106.1
U1_SOUT_N: C144.2 R95.2 R96.2 U1.5(S_OUTN)
U1_SOUT_N_U2_SIN_N: R96.1 R105.1
U1_SOUT_P: C145.2 R93.2 R94.2 U1.4(S_OUTP)
U1_SOUT_P_U2_SIN_P: R93.1 R97.1
U1_TX_CLK: JP55.11 R138.1 R142.1 U1.53(TX_CLK)
U1_TX_CLK1: JP24.11 R142.2
U1_TX_CTRL: JP24.1 JP55.1 U1.56(TX_CTRL)
U1_TXD_0: JP24.3 JP55.3 U1.50(TXD[0])
U1_TXD_1: JP24.5 JP55.5 U1.51(TXD[1])
U1_TXD_2: JP24.7 JP55.7 U1.54(TXD[2])
U1_TXD_3: JP24.9 JP55.9 U1.55(TXD[3])
U1_V18: JP4.1 R8.2 U1.10(VDDO_SEL)
U1_VDD_1.0V: C8.1 C9.1 C10.1 C11.1 C12.1 C13.1 C15.1 C185.1 C186.1 L15.1 TP23.1(TP) U1.6(DVDD#6) U1.40(DVDD_OUT) U1.42(DVDD#42)
U1_VDD_3.3V: C22.1 C46.1 C47.1 C48.1 C49.1 C50.1 C194.1 C195.1 C196.1 L18.1 TP25.1(TP) U1.36(REG_IN)
U1_VDDO: C16.1 C17.1 C18.1 C19.1 C20.1 C21.1 C176.1 C177.1 L13.1 TP21.1(TP) U1.11(VDDO#11) U1.49(VDDO#49) U1.52(VDDO#52)
U1_XTAL1: R3.1 R4.2 R5.2 U1.34(XTAL1)
U1_XTAL2: R6.1 U1.33(XTAL2)
U2_1.8V: JP31.1 JP32.1 JP33.1 JP34.1
U2_AVDD_1.8V: C80.1 C81.1 C82.1 C83.1 C84.1 C85.1 C86.1 C87.1 C170.1 C171.1 L9.1 TP18.1(TP) U2.19(AVDD18#19) U2.26(AVDD18#26) U2.38(AVDD18#38) U2.39(AVDD18_OUT)
U2_AVDD_3.3V: C88.1 C89.1 C90.1 C91.1 C92.1 C207.1 C208.1 L22.1 TP28.1(TP) U2.20(AVDD33#20) U2.25(AVDD33#25)
U2_AVDDC_1.8V: C76.1 C77.1 C78.1 C79.1 C172.1 C173.1 L10.1 TP19.1(TP) U2.35(AVDDC18)
U2_AVDDF_1.8V: C72.1 C73.1 C74.1 C75.1 C174.1 C175.1 L11.1 TP20.1(TP) U2.3(AVDD18#3)
U2_CLK125: C63.1 J10.1 U2.9(CLK125)
U2_CONFIG: JP58.1 R150.1 U2.15(CONFIG)
U2_LED_0: JP13.5 R31.2 U2.14(LED[0])
U2_LED_1: JP13.3 JP54.1 R164.1 U2.13(LED[1])
U2_LED_2: INTN_2.1(TP) JP14.1 U2.12(LED[2]/INTN)
U2_MDC: U2.7(MDC) U4.6(2Y)
U2_MDI_N_0: R67.2 R68.1 U2.27(MDIN[0])
U2_MDI_N_1: R72.2 R73.1 U2.23(MDIN[1])
U2_MDI_N_2: R77.2 R78.1 U2.21(MDIN[2])
U2_MDI_N_3: R82.2 R83.1 U2.17(MDIN[3])
U2_MDI_P_0: R64.1 R65.2 U2.28(MDIP[0])
U2_MDI_P_1: R69.1 R70.2 U2.24(MDIP[1])
U2_MDI_P_2: R74.1 R75.2 U2.22(MDIP[2])
U2_MDI_P_3: R79.1 R80.2 U2.18(MDIP[3])
U2_RESETN: JP3.2 R2.2 U2.16(RESETN)
U2_RX_CLK: R139.1 R141.2 U2.46(RX_CLK)
U2_RX_CLK1: JP24.12 R141.1
U2_RX_CTRL: JP24.2 U2.43(RX_CTRL)
U2_RXD_0: JP24.4 U2.44(RXD[0])
U2_RXD_1: JP24.6 U2.45(RXD[1])
U2_RXD_2: JP24.8 U2.47(RXD[2])
U2_RXD_3: JP24.10 U2.48(RXD[3])
U2_SIN_N: C147.1 R99.2 R105.2 U2.2(S_INN)
U2_SIN_P: C146.1 R97.2 R98.2 U2.1(S_INP)
U2_SOUT_N: C154.2 R108.2 R109.2 U2.5(S_OUTN)
U2_SOUT_P: C155.2 R106.2 R107.2 U2.4(S_OUTP)
U2_TX_CLK: JP53.11 R137.1 R143.2 U2.53(TX_CLK)
U2_TX_CLK1: JP23.12 R143.1
U2_TX_CTRL: JP23.2 JP53.1 U2.56(TX_CTRL)
U2_TXD_0: JP23.4 JP53.3 U2.50(TXD[0])
U2_TXD_1: JP23.6 JP53.5 U2.51(TXD[1])
U2_TXD_2: JP23.8 JP53.7 U2.54(TXD[2])
U2_TXD_3: JP23.10 JP53.9 U2.55(TXD[3])
U2_V18: JP8.1 R24.2 U2.10(VDDO_SEL)
U2_VDD_1.0V: C58.1 C59.1 C60.1 C61.1 C62.1 C64.1 C191.1 C193.1 L17.1 TP24.1(TP) U2.6(DVDD#6) U2.40(DVDD_OUT) U2.42(DVDD#42)
U2_VDD_3.3V: C93.1 C94.1 C95.1 C96.1 C97.1 C197.1 C198.1 L19.1 TP26.1(TP) U2.36(REG_IN)
U2_VDDO: C65.1 C66.1 C67.1 C68.1 C69.1 C70.1 C182.1 C184.1 L14.1 TP22.1(TP) U2.11(VDDO#11) U2.49(VDDO#49) U2.52(VDDO#52)
U2_XTAL1: R17.1 R18.2 R19.2 U2.34(XTAL1)
U2_XTAL2: R21.1 U2.33(XTAL2)
N16787604: D3.2 R30.1
N16796830: JP1.1 Y1.1(EN)
N16796833: R4.1 Y1.3(OUT)
N16796834: C3.1 J1.1 R3.2
N16796839: C6.1 R5.1 Y2.2
N16994346: R10.2 R11.2 R14.1 U1.32(HSDACP)
N16994348: R12.2 R15.1 R16.1 U1.31(HSDACN)
N17016825: C54.1 J8.1 R17.2
N17016957: R18.1 Y3.3(OUT)
N17016970: C55.1 R19.1 Y4.2
N17016978: C56.1 R20.1 R21.2
N17193751: JP2.3 U3.2(R\E\S\E\T\)
N17251537: JP13.2 JP13.4 JP13.6 JP13.8 JP58.2
N17251820: D6.2 R33.1
N17493866: JP5.2 R12.1
N17495532: JP5.1 R11.1
N17503153: JP7.1 Y3.1(EN)
N17787307: JP2.2 JP3.1 JP3.3
N17830081: JP11.2 JP11.4 JP11.6 JP11.8 JP57.2
N17893687: R65.1 U6.11(TRD1_P)
N17893693: R67.1 U6.10(TRD1_M)
N17893695: R70.1 U6.4(TRD2_P)
N17893699: R75.1 U6.3(TRD3_P)
N17893703: R77.1 U6.2(TRD3_M)
N17893707: R80.1 U6.8(TRD4_P)
N17893711: R82.1 U6.9(TRD4_M)
N18175709: R72.1 U6.5(TRD2_M)
N18237123: R13.1 U1.30(RSET)
N18290180: JP17.1 R48.2 R50.1
N18290184: JP17.2 R50.2 R53.2
N18290198: R57.1 U5.2(TD1_P)
N18290204: R55.1 U5.3(TD1_M)
N18290208: R51.1 U5.5(TD2_P)
N18290216: R49.1 U5.6(TD2_M)
N18290228: R45.1 U5.8(TD3_P)
N18290246: JP18.1 R54.2 R56.1
N18290250: JP18.2 R56.2 R59.2
N18290323: R43.1 U5.9(TD3_M)
N18290640: JP15.1 R37.1 R40.2
N18290658: JP15.2 R37.2 R42.2
N18290664: CON1.2(DA_M) U5.14(MX4_P)
N18290670: CON1.1(DA_P) U5.13(MX4_M)
N18290676: CON1.3(DB_P) U5.16(MX3_M)
N18290682: CON1.6(DB_M) U5.17(MX3_P)
N18290688: CON1.4(DC_P) U5.19(MX2_M)
N18290694: CON1.5(DC_M) U5.20(MX2_P)
N18290700: CON1.7(DD_P) U5.22(MX1_M)
N18290706: CON1.8(DD_M) U5.23(MX1_P)
N18290712: C105.1 R38.1
N18290718: C118.1 R52.2 U5.21(MCT2)
N18290720: C120.1 R58.2 U5.24(MCT1)
N18290726: C100.1 R38.2 U5.15(MCT4)
N18290728: C109.1 R46.1
N18290732: C113.1 R52.1
N18290736: C98.1 R46.2 U5.18(MCT3)
N18290738: C117.1 R58.1
N18290828: R36.1 U5.12(TD4_M)
N18290888: JP16.1 R39.2 R44.1
N18290892: JP16.2 R44.2 R47.2
N18290908: R41.1 U5.11(TD4_P)
N18307922: JP19.1 R64.2 R66.1
N18307926: JP19.2 R66.2 R68.2
N18317435: JP20.1 R69.2 R71.1
N18317437: JP20.2 R71.2 R73.2
N18317956: JP21.1 R74.2 R76.1
N18317958: JP21.2 R76.2 R78.2
N18318493: JP22.1 R79.2 R81.1
N18318495: JP22.2 R81.2 R83.2
N18570142: JP12.2 R30.2
N18601588: JP6.1 U1.29(TSTPT)
N18793953: C7.1 R6.2 Y2.1
N19074906: JP10.1 U2.29(TSTPT)
N19074920: R25.1 U2.30(RSET)
N19074934: JP9.1 R27.1 U2.31(HSDACN)
N19074982: JP9.2 R26.1 U2.32(HSDACP)
N19224300: JP47.1 JP48.1 JP49.2 JP50.1 JP52.1
N19224342: C190.2 C192.2 JP46.2 R130.1 U11.8(PVIN)
N19224390: C202.2 C205.2 JP51.2 R135.1 U12.8(PVIN)
N19224537: JP50.2 L21.2
N19224649: C201.1 R135.2 U12.1(ILIM) U12.9(SVIN)
N19224675: R126.1 U11.14(VSET)
N19224677: L16.1 U11.5(SW1) U11.7(SW2)
N19224683: C189.1 R130.2 U11.1(ILIM) U11.9(SVIN)
N19224747: R128.1 U11.15(PSET)
N19224753: JP43.2 L15.2
N19224758: JP43.1 JP44.2 JP45.1
N19224792: D11.1 R131.2
N19224808: R132.2 U12.14(VSET)
N19224948: L20.1 U12.5(SW1) U12.7(SW2)
N19224958: JP52.2 L22.2
N19224996: R133.1 U12.15(PSET)
N19225038: JP45.2 L17.2
N19225131: D10.1 R125.2
N19227820: JP39.2 JP40.1 JP41.1
N19228113: JP26.2 L6.2
N19228189: C181.2 C183.2 JP42.2 R123.1 U10.8(PVIN)
N19228203: R113.2 U9.14(VSET)
N19228243: C168.2 C169.2 JP30.2 R116.1 U9.8(PVIN)
N19228291: C167.1 R116.2 U9.1(ILIM) U9.9(SVIN)
N19228315: JP25.2 L5.2
N19228347: C165.1 C166.1 JP29.2 L7.2 R112.1 U9.3(SFB)
N19228371: JP35.2 JP36.2 JP37.2 JP38.2 U10.14(VSET)
N19228441: D8.1 R110.2
N19228445: D9.1 R117.2
N19228465: L7.1 U9.5(SW1) U9.7(SW2)
N19228523: R114.1 U9.15(PSET)
N19228594: JP28.2 L8.2
N19228794: JP41.2 L14.2
N19228818: JP40.2 L13.2
N19228834: L12.1 U10.5(SW1) U10.7(SW2)
N19228838: C180.1 R123.2 U10.1(ILIM) U10.9(SVIN)
N19228887: R118.1 U10.15(PSET)
N19228961: JP27.2 JP29.1 JP31.2
N19229117: JP33.2 L10.2
N19229193: JP32.2 L9.2
N19229239: JP34.2 L11.2
N19229269: JP36.1 R120.1
N19229277: C159.1 C160.1 F1.1 J20.1 J20.2
N19229287: D7.1 R111.1
N19241861: C142.1 L2.1 U7.15(VCCR)
N19242097: C145.1 J14.1
N19242099: C144.1 J13.1
N19242143: C138.1 C139.1 L1.2 U7.16(VCCT)
N19242271: C136.2 J11.1
N19242275: C137.2 J12.1
N19242333: R94.1 U7.18(TD+)
N19242335: R95.1 U7.19(TD-)
N19242343: R85.1 U7.13(RD+)
N19242345: R86.1 U7.12(RD-)
N19242395: R89.1 U7.6(MOD-DEF_0)
N19242397: R90.1 U7.5(MOD-DEF_1)
N19242401: R91.1 U7.4(MOD-DEF_2)
N19242403: R92.1 U7.2(TXFAULT)
N19242417: R88.1 U7.8(LOS)
N19251259: C152.1 L4.1 U8.15(VCCR)
N19251492: C155.1 J18.1
N19251494: C154.1 J17.1
N19251531: C148.1 C149.1 L3.2 U8.16(VCCT)
N19251660: C146.2 J15.1
N19251670: C147.2 J16.1
N19251724: R107.1 U8.18(TD+)
N19251726: R108.1 U8.19(TD-)
N19251738: R98.1 U8.13(RD+)
N19251740: R99.1 U8.12(RD-)
N19251790: R101.1 U8.6(MOD-DEF_0)
N19251792: R102.1 U8.5(MOD-DEF_1)
N19251796: R103.1 U8.4(MOD-DEF_2)
N19251798: R104.1 U8.2(TXFAULT)
N19251812: R100.1 U8.8(LOS)
N19271739: C24.1 U1.41(REGCAP2)
N19272342: C24.2 U1.37(REGCAP1)
N19279105: C71.1 U2.41(REGCAP2)
N19280044: C71.2 U2.37(REGCAP1)
N19304511: C102.1 C103.1 C104.1 U5.10(TCT4)
N19306537: C106.1 C107.1 C108.1 U5.7(TCT3)
N19306786: C110.1 C111.1 C112.1 U5.4(TCT2)
N19307065: C114.1 C115.1 C116.1 U5.1(TCT1)
N19311353: C124.1 C125.1 C126.1 U6.12(TRCT1)
N19311558: C127.1 C128.1 C129.1 U6.6(TRCT2)
N19311775: C130.1 C131.1 C132.1 U6.1(TRCT3)
N19312774: C133.1 C134.1 C135.1 U6.7(TRCT4)
N19315408: C100.2 R35.1
N19315410: C101.1 R35.2
N19317022: C118.2 R60.1
N19317024: C119.1 R60.2
N19317288: C120.2 R61.1
N19317290: C121.1 R61.2
N19317557: C98.2 R34.1
N19317559: C99.1 R34.2
N19395566: C57.1 R23.2
N19411569: R20.2 Y4.1
N19626709: C23.1 R9.1 TP29.1(TP) U1.39(AVDD18_OUT)
N19642082: J6.1 R10.1
N19649053: J7.1 R16.2
N19710537: JP47.2 L18.2
N19710593: JP48.2 L19.2
N19712055: C194.2 J22.1
N19732438: C22.2 J4.1
N19876023: JP35.1 R119.1
N19879807: JP37.1 R121.1
N19880091: JP38.1 R122.1
N20143388: SW1.1 SW1.4 U3.3(M\R\)
N20247366: J26.1 R139.2
N20247420: J25.1 R137.2
N20250415: J24.1 R136.2
N20252579: J27.1 R138.2
N20326527: C23.2 J5.1
N20344726: C15.2 J3.1
N20356781: C156.2 J19.1
N20368817: C203.2 J23.1
N20438631: JP11.7 R146.2
N20438658: JP11.1 R145.2
N20438885: JP13.7 R147.2
N20438965: JP13.1 R148.1
N20443701: JP53.2 R156.1
N20443710: JP53.4 R155.1
N20443719: JP53.6 R154.1
N20444304: JP53.8 R153.1
N20444313: JP53.10 R152.1
N20444322: JP53.12 R151.1
N20444660: JP55.2 R162.1
N20444664: JP55.4 R161.1
N20444668: JP55.6 R159.1
N20444672: JP55.8 R160.1
N20444676: JP55.10 R158.1
N20444680: JP55.12 R157.1
N20445311: J28.1 R149.2
N20445323: J29.1 R150.2
N20445616: JP14.2 R33.2
N20445860: J31.1 R164.2
N20445926: JP54.2 R32.2
N20446666: JP56.2 R29.2
N20446778: J30.1 R163.2
N171467441: D4.2 R31.1
N171467701: D1.2 R28.1
N171468251: D5.2 R32.1
